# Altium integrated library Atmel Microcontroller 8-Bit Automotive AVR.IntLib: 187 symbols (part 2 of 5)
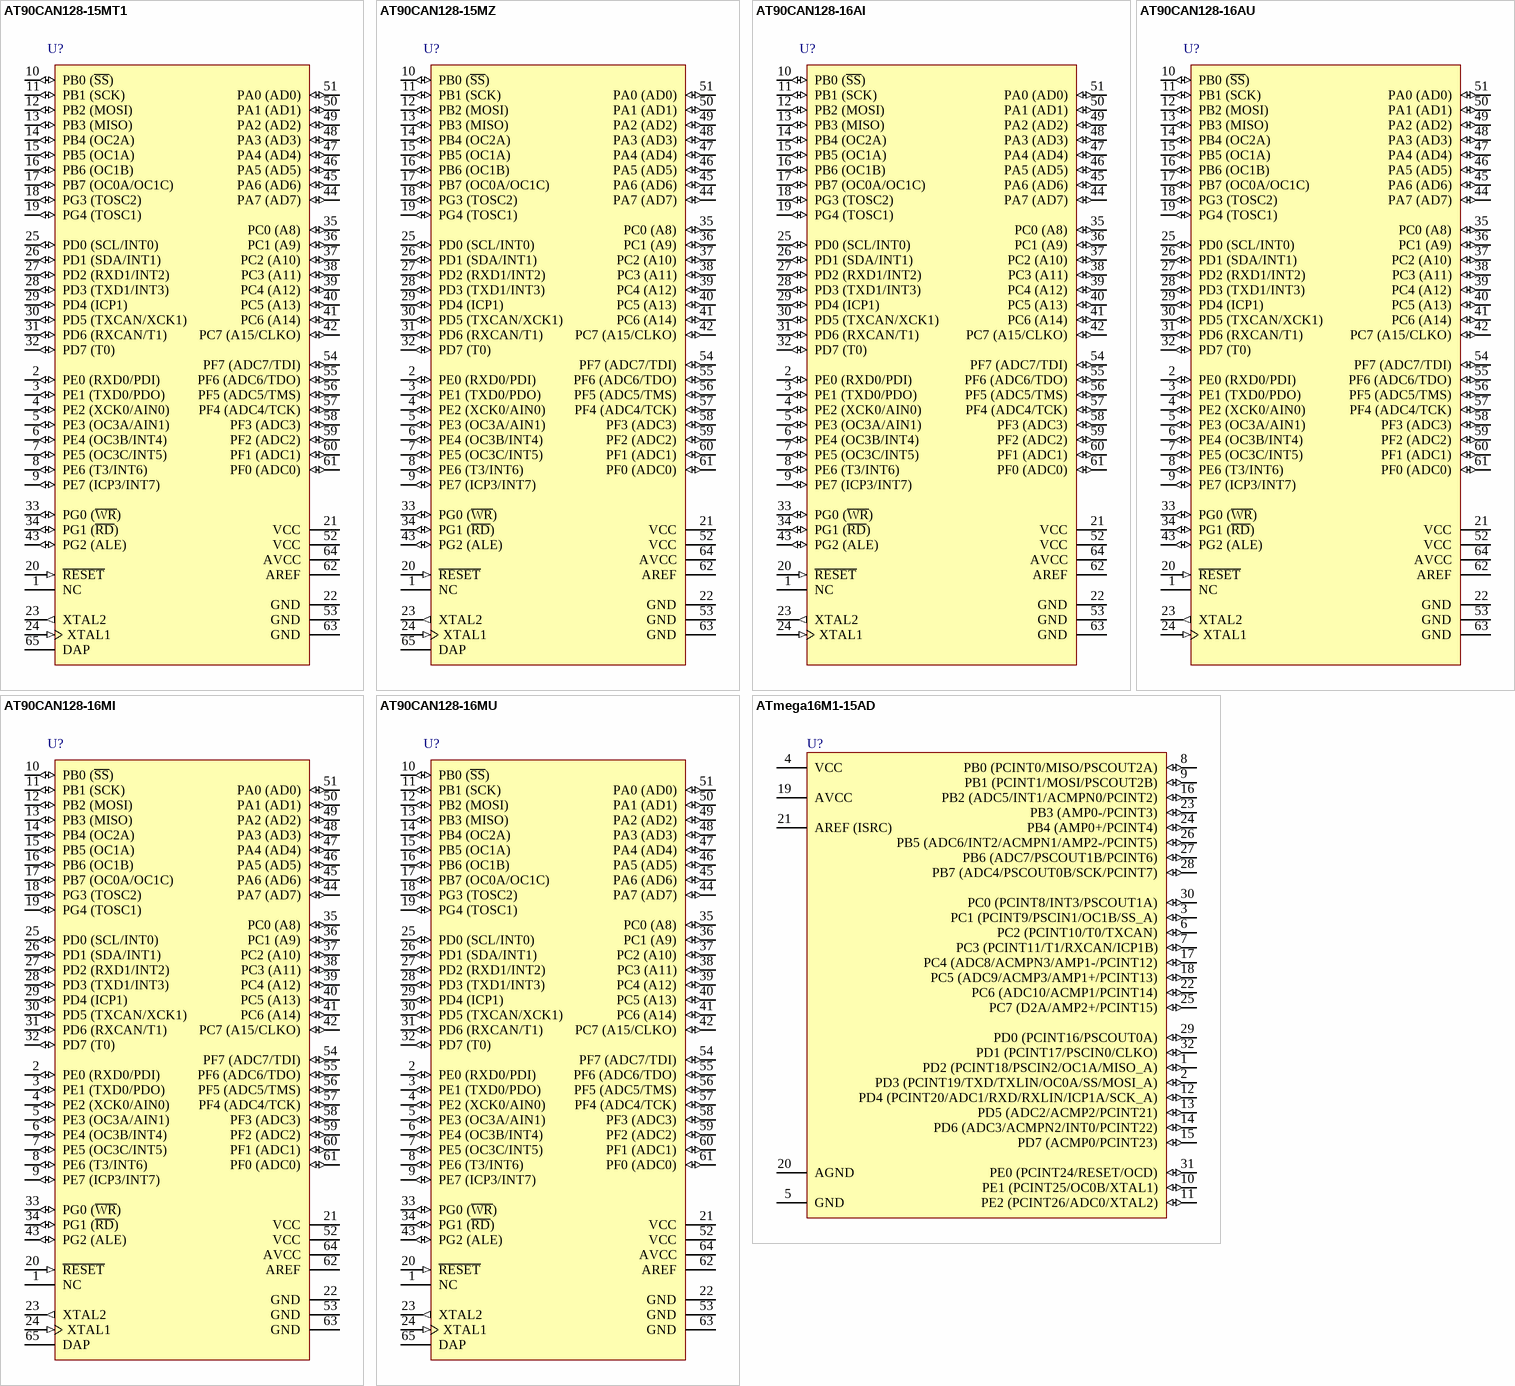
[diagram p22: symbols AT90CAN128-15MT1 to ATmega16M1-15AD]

## AT90CAN128-16MU
designator U?
8-bit AVR Microcontroller, 128KB Flash and CAN Controller, 53 GPIO pins, Industrial Grade (-40° to +85°C), 64-pin VQFN, Green
footprint Z64-2_N (QFN, 64-Leads, Body 9x9mm, Pitch 0.5mm, IPC Medium Density)
footprint Z64-2_L (QFN, 64-Leads, Body 9x9mm, Pitch 0.5mm, IPC High Density)
footprint Z64-2_M (QFN, 64-Leads, Body 9x9mm, Pitch 0.5mm, IPC Low Density)
pins: 1 NC, 2 PE0 (RXD0/PDI) (io), 3 PE1 (TXD0/PDO) (io), 4 PE2 (XCK0/AIN0) (io), 5 PE3 (OC3A/AIN1) (io), 6 PE4 (OC3B/INT4) (io), 7 PE5 (OC3C/INT5) (io), 8 PE6 (T3/INT6) (io), 9 PE7 (ICP3/INT7) (io), 10 PB0 (~{SS}) (io), 11 PB1 (SCK) (io), 12 PB2 (MOSI) (io), 13 PB3 (MISO) (io), 14 PB4 (OC2A) (io), 15 PB5 (OC1A) (io), 16 PB6 (OC1B) (io), 17 PB7 (OC0A/OC1C) (io), 18 PG3 (TOSC2) (io), 19 PG4 (TOSC1) (io), 20 ~{RESET} (in), 21 VCC (power), 22 GND (power), 23 XTAL2 (out), 24 XTAL1 (in), 25 PD0 (SCL/INT0) (io), 26 PD1 (SDA/INT1) (io), 27 PD2 (RXD1/INT2) (io), 28 PD3 (TXD1/INT3) (io), 29 PD4 (ICP1) (io), 30 PD5 (TXCAN/XCK1) (io), 31 PD6 (RXCAN/T1) (io), 32 PD7 (T0) (io), 33 PG0 (~{WR}) (io), 34 PG1 (~{RD}) (io), 35 PC0 (A8) (io), 36 PC1 (A9) (io), 37 PC2 (A10) (io), 38 PC3 (A11) (io), 39 PC4 (A12) (io), 40 PC5 (A13) (io), 41 PC6 (A14) (io), 42 PC7 (A15/CLKO) (io), 43 PG2 (ALE) (io), 44 PA7 (AD7) (io), 45 PA6 (AD6) (io), 46 PA5 (AD5) (io), 47 PA4 (AD4) (io), 48 PA3 (AD3) (io), 49 PA2 (AD2) (io), 50 PA1 (AD1) (io), 51 PA0 (AD0) (io), 52 VCC (power), 53 GND (power), 54 PF7 (ADC7/TDI) (io), 55 PF6 (ADC6/TDO) (io), 56 PF5 (ADC5/TMS) (io), 57 PF4 (ADC4/TCK) (io), 58 PF3 (ADC3) (io), 59 PF2 (ADC2) (io), 60 PF1 (ADC1) (io), 61 PF0 (ADC0) (io), 62 AREF (power), 63 GND (power), 64 AVCC (power), 65 DAP (power)

## ATmega16M1-15AD
designator U?
8-bit Automotive AVR Microcontroller, 16KB Flash, 512 Bytes EEPROM, 1KB SRAM, Extended Grade (-40°C to +150°C), 32-Pin TQFP
footprint 32MA_N (Thin QFP, 32-Leads, Body 7x7mm, Pitch 0.8mm, IPC Medium Density)
footprint 32MA_L (Thin QFP, 32-Leads, Body 7x7mm, Pitch 0.8mm, IPC High Density)
footprint 32MA_M (Thin QFP, 32-Leads, Body 7x7mm, Pitch 0.8mm, IPC Low Density)
pins: 1 PD2 (PCINT18/PSCIN2/OC1A/MISO_A) (io), 2 PD3 (PCINT19/TXD/TXLIN/OC0A/SS/MOSI_A) (io), 3 PC1 (PCINT9/PSCIN1/OC1B/SS_A) (io), 4 VCC (power), 5 GND (power), 6 PC2 (PCINT10/T0/TXCAN) (io), 7 PC3 (PCINT11/T1/RXCAN/ICP1B) (io), 8 PB0 (PCINT0/MISO/PSCOUT2A) (io), 9 PB1 (PCINT1/MOSI/PSCOUT2B) (io), 10 PE1 (PCINT25/OC0B/XTAL1) (io), 11 PE2 (PCINT26/ADC0/XTAL2) (io), 12 PD4 (PCINT20/ADC1/RXD/RXLIN/ICP1A/SCK_A) (io), 13 PD5 (ADC2/ACMP2/PCINT21) (io), 14 PD6 (ADC3/ACMPN2/INT0/PCINT22) (io), 15 PD7 (ACMP0/PCINT23) (io), 16 PB2 (ADC5/INT1/ACMPN0/PCINT2) (io), 17 PC4 (ADC8/ACMPN3/AMP1-/PCINT12) (io), 18 PC5 (ADC9/ACMP3/AMP1+/PCINT13) (io), 19 AVCC (power), 20 AGND (power), 21 AREF (ISRC) (power), 22 PC6 (ADC10/ACMP1/PCINT14) (io), 23 PB3 (AMP0-/PCINT3) (io), 24 PB4 (AMP0+/PCINT4) (io), 25 PC7 (D2A/AMP2+/PCINT15) (io), 26 PB5 (ADC6/INT2/ACMPN1/AMP2-/PCINT5) (io), 27 PB6 (ADC7/PSCOUT1B/PCINT6) (io), 28 PB7 (ADC4/PSCOUT0B/SCK/PCINT7) (io), 29 PD0 (PCINT16/PSCOUT0A) (io), 30 PC0 (PCINT8/INT3/PSCOUT1A) (io), 31 PE0 (PCINT24/RESET/OCD) (io), 32 PD1 (PCINT17/PSCIN0/CLKO) (io)

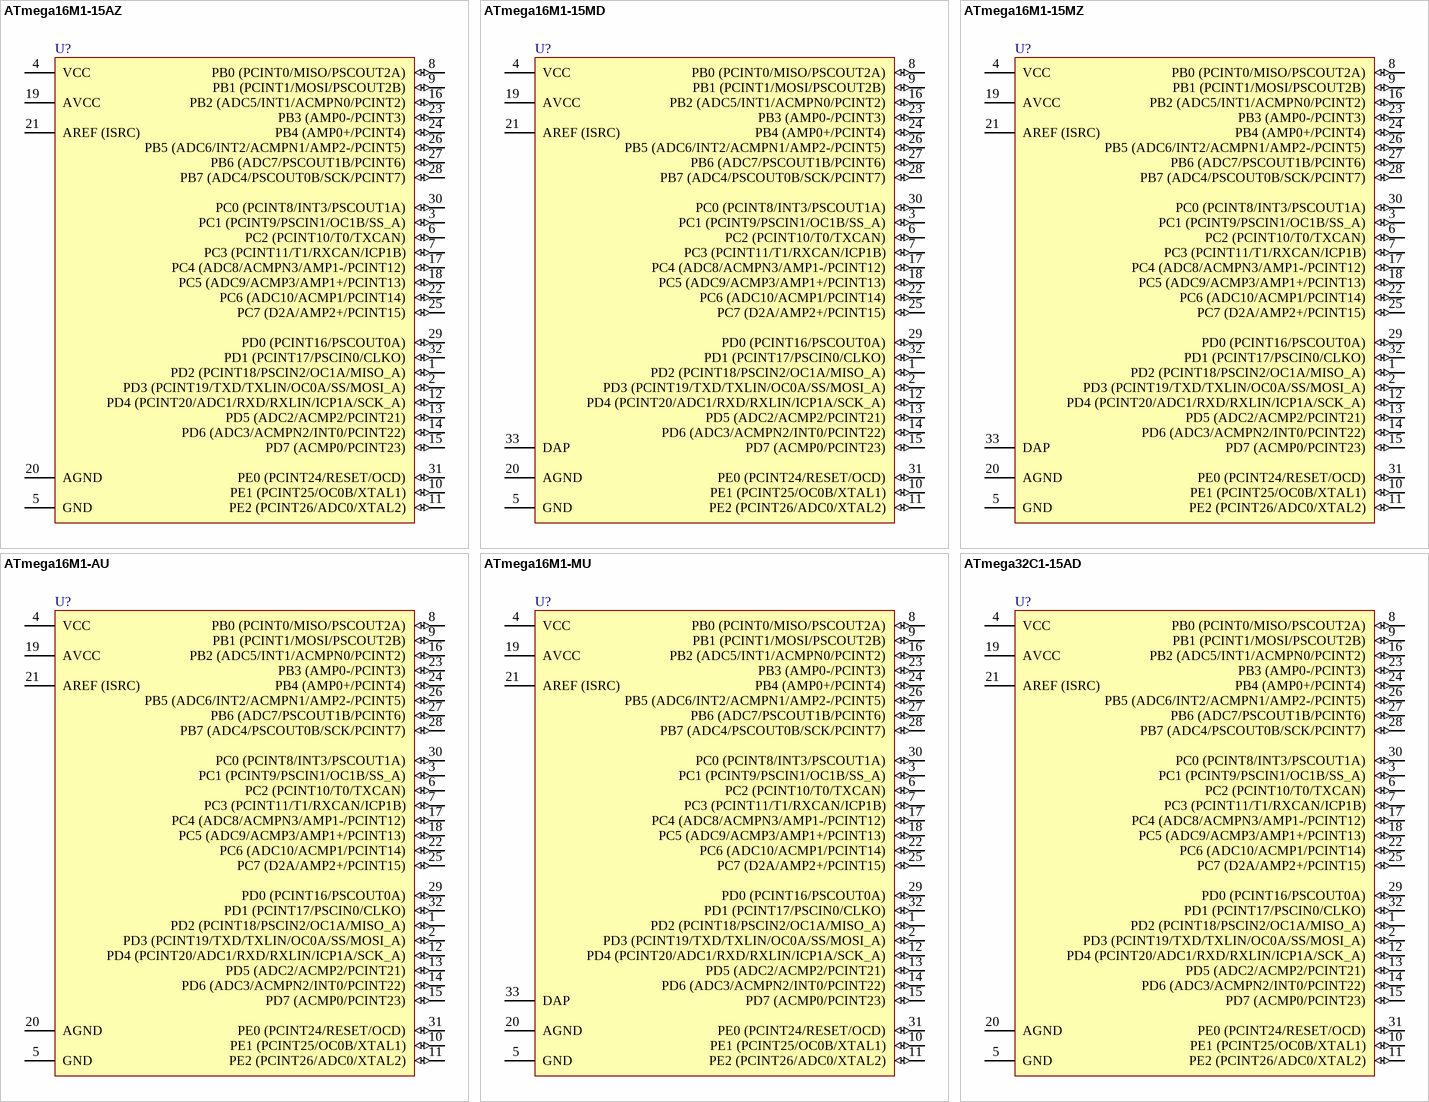
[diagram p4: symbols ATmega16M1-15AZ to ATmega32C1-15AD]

## ATmega16M1-15AZ
designator U?
8-bit Automotive AVR Microcontroller, 16KB Flash, 512 Bytes EEPROM, 1KB SRAM, PSC, Automotive Grade (-40°C to +125°C), 32-Pin TQFP
footprint 32MA_N (Thin QFP, 32-Leads, Body 7x7mm, Pitch 0.8mm, IPC Medium Density)
footprint 32MA_L (Thin QFP, 32-Leads, Body 7x7mm, Pitch 0.8mm, IPC High Density)
footprint 32MA_M (Thin QFP, 32-Leads, Body 7x7mm, Pitch 0.8mm, IPC Low Density)
pins: 1 PD2 (PCINT18/PSCIN2/OC1A/MISO_A) (io), 2 PD3 (PCINT19/TXD/TXLIN/OC0A/SS/MOSI_A) (io), 3 PC1 (PCINT9/PSCIN1/OC1B/SS_A) (io), 4 VCC (power), 5 GND (power), 6 PC2 (PCINT10/T0/TXCAN) (io), 7 PC3 (PCINT11/T1/RXCAN/ICP1B) (io), 8 PB0 (PCINT0/MISO/PSCOUT2A) (io), 9 PB1 (PCINT1/MOSI/PSCOUT2B) (io), 10 PE1 (PCINT25/OC0B/XTAL1) (io), 11 PE2 (PCINT26/ADC0/XTAL2) (io), 12 PD4 (PCINT20/ADC1/RXD/RXLIN/ICP1A/SCK_A) (io), 13 PD5 (ADC2/ACMP2/PCINT21) (io), 14 PD6 (ADC3/ACMPN2/INT0/PCINT22) (io), 15 PD7 (ACMP0/PCINT23) (io), 16 PB2 (ADC5/INT1/ACMPN0/PCINT2) (io), 17 PC4 (ADC8/ACMPN3/AMP1-/PCINT12) (io), 18 PC5 (ADC9/ACMP3/AMP1+/PCINT13) (io), 19 AVCC (power), 20 AGND (power), 21 AREF (ISRC) (power), 22 PC6 (ADC10/ACMP1/PCINT14) (io), 23 PB3 (AMP0-/PCINT3) (io), 24 PB4 (AMP0+/PCINT4) (io), 25 PC7 (D2A/AMP2+/PCINT15) (io), 26 PB5 (ADC6/INT2/ACMPN1/AMP2-/PCINT5) (io), 27 PB6 (ADC7/PSCOUT1B/PCINT6) (io), 28 PB7 (ADC4/PSCOUT0B/SCK/PCINT7) (io), 29 PD0 (PCINT16/PSCOUT0A) (io), 30 PC0 (PCINT8/INT3/PSCOUT1A) (io), 31 PE0 (PCINT24/RESET/OCD) (io), 32 PD1 (PCINT17/PSCIN0/CLKO) (io)

## ATmega16M1-15MD
designator U?
8-bit Automotive AVR Microcontroller, 16KB Flash, 512 Bytes EEPROM, 1KB SRAM, Extended Grade (-40°C to +150°C), 32-Pin VQFN
footprint 32PV_N (QFN, 32-Leads, Body 7x7 mm, Pitch 0.65mm, IPC Medium Density)
footprint 32PV_L (QFN, 32-Leads, Body 7x7 mm, Pitch 0.65mm, IPC High Density)
footprint 32PV_M (QFN, 32-Leads, Body 7x7 mm, Pitch 0.65mm, IPC Low Density)
pins: 1 PD2 (PCINT18/PSCIN2/OC1A/MISO_A) (io), 2 PD3 (PCINT19/TXD/TXLIN/OC0A/SS/MOSI_A) (io), 3 PC1 (PCINT9/PSCIN1/OC1B/SS_A) (io), 4 VCC (power), 5 GND (power), 6 PC2 (PCINT10/T0/TXCAN) (io), 7 PC3 (PCINT11/T1/RXCAN/ICP1B) (io), 8 PB0 (PCINT0/MISO/PSCOUT2A) (io), 9 PB1 (PCINT1/MOSI/PSCOUT2B) (io), 10 PE1 (PCINT25/OC0B/XTAL1) (io), 11 PE2 (PCINT26/ADC0/XTAL2) (io), 12 PD4 (PCINT20/ADC1/RXD/RXLIN/ICP1A/SCK_A) (io), 13 PD5 (ADC2/ACMP2/PCINT21) (io), 14 PD6 (ADC3/ACMPN2/INT0/PCINT22) (io), 15 PD7 (ACMP0/PCINT23) (io), 16 PB2 (ADC5/INT1/ACMPN0/PCINT2) (io), 17 PC4 (ADC8/ACMPN3/AMP1-/PCINT12) (io), 18 PC5 (ADC9/ACMP3/AMP1+/PCINT13) (io), 19 AVCC (power), 20 AGND (power), 21 AREF (ISRC) (power), 22 PC6 (ADC10/ACMP1/PCINT14) (io), 23 PB3 (AMP0-/PCINT3) (io), 24 PB4 (AMP0+/PCINT4) (io), 25 PC7 (D2A/AMP2+/PCINT15) (io), 26 PB5 (ADC6/INT2/ACMPN1/AMP2-/PCINT5) (io), 27 PB6 (ADC7/PSCOUT1B/PCINT6) (io), 28 PB7 (ADC4/PSCOUT0B/SCK/PCINT7) (io), 29 PD0 (PCINT16/PSCOUT0A) (io), 30 PC0 (PCINT8/INT3/PSCOUT1A) (io), 31 PE0 (PCINT24/RESET/OCD) (io), 32 PD1 (PCINT17/PSCIN0/CLKO) (io), 33 DAP (power)

## ATmega16M1-15MZ
designator U?
8-bit Automotive AVR Microcontroller, 16KB Flash, 512 Bytes EEPROM, 1KB SRAM, PSC, Automotive Grade (-40°C to +125°C), 32-Pin VQFN
footprint 32PV_N (QFN, 32-Leads, Body 7x7 mm, Pitch 0.65mm, IPC Medium Density)
footprint 32PV_L (QFN, 32-Leads, Body 7x7 mm, Pitch 0.65mm, IPC High Density)
footprint 32PV_M (QFN, 32-Leads, Body 7x7 mm, Pitch 0.65mm, IPC Low Density)
pins: 1 PD2 (PCINT18/PSCIN2/OC1A/MISO_A) (io), 2 PD3 (PCINT19/TXD/TXLIN/OC0A/SS/MOSI_A) (io), 3 PC1 (PCINT9/PSCIN1/OC1B/SS_A) (io), 4 VCC (power), 5 GND (power), 6 PC2 (PCINT10/T0/TXCAN) (io), 7 PC3 (PCINT11/T1/RXCAN/ICP1B) (io), 8 PB0 (PCINT0/MISO/PSCOUT2A) (io), 9 PB1 (PCINT1/MOSI/PSCOUT2B) (io), 10 PE1 (PCINT25/OC0B/XTAL1) (io), 11 PE2 (PCINT26/ADC0/XTAL2) (io), 12 PD4 (PCINT20/ADC1/RXD/RXLIN/ICP1A/SCK_A) (io), 13 PD5 (ADC2/ACMP2/PCINT21) (io), 14 PD6 (ADC3/ACMPN2/INT0/PCINT22) (io), 15 PD7 (ACMP0/PCINT23) (io), 16 PB2 (ADC5/INT1/ACMPN0/PCINT2) (io), 17 PC4 (ADC8/ACMPN3/AMP1-/PCINT12) (io), 18 PC5 (ADC9/ACMP3/AMP1+/PCINT13) (io), 19 AVCC (power), 20 AGND (power), 21 AREF (ISRC) (power), 22 PC6 (ADC10/ACMP1/PCINT14) (io), 23 PB3 (AMP0-/PCINT3) (io), 24 PB4 (AMP0+/PCINT4) (io), 25 PC7 (D2A/AMP2+/PCINT15) (io), 26 PB5 (ADC6/INT2/ACMPN1/AMP2-/PCINT5) (io), 27 PB6 (ADC7/PSCOUT1B/PCINT6) (io), 28 PB7 (ADC4/PSCOUT0B/SCK/PCINT7) (io), 29 PD0 (PCINT16/PSCOUT0A) (io), 30 PC0 (PCINT8/INT3/PSCOUT1A) (io), 31 PE0 (PCINT24/RESET/OCD) (io), 32 PD1 (PCINT17/PSCIN0/CLKO) (io), 33 DAP (power)

## ATmega16M1-AU
designator U?
8-bit AVR Microcontroller, 16KB Flash, 512 Bytes EEPROM, 1KB SRAM, Industrial Grade (-40° to +85°C), 32-Pin TQFP
footprint 32A_N (Thin QFP, 32-Leads, Body 7x7mm, Pitch 0.8mm, IPC Medium Density)
footprint 32A_L (Thin QFP, 32-Leads, Body 7x7mm, Pitch 0.8mm, IPC High Density)
footprint 32A_M (Thin QFP, 32-Leads, Body 7x7mm, Pitch 0.8mm, IPC Low Density)
pins: 1 PD2 (PCINT18/PSCIN2/OC1A/MISO_A) (io), 2 PD3 (PCINT19/TXD/TXLIN/OC0A/SS/MOSI_A) (io), 3 PC1 (PCINT9/PSCIN1/OC1B/SS_A) (io), 4 VCC (power), 5 GND (power), 6 PC2 (PCINT10/T0/TXCAN) (io), 7 PC3 (PCINT11/T1/RXCAN/ICP1B) (io), 8 PB0 (PCINT0/MISO/PSCOUT2A) (io), 9 PB1 (PCINT1/MOSI/PSCOUT2B) (io), 10 PE1 (PCINT25/OC0B/XTAL1) (io), 11 PE2 (PCINT26/ADC0/XTAL2) (io), 12 PD4 (PCINT20/ADC1/RXD/RXLIN/ICP1A/SCK_A) (io), 13 PD5 (ADC2/ACMP2/PCINT21) (io), 14 PD6 (ADC3/ACMPN2/INT0/PCINT22) (io), 15 PD7 (ACMP0/PCINT23) (io), 16 PB2 (ADC5/INT1/ACMPN0/PCINT2) (io), 17 PC4 (ADC8/ACMPN3/AMP1-/PCINT12) (io), 18 PC5 (ADC9/ACMP3/AMP1+/PCINT13) (io), 19 AVCC (power), 20 AGND (power), 21 AREF (ISRC) (power), 22 PC6 (ADC10/ACMP1/PCINT14) (io), 23 PB3 (AMP0-/PCINT3) (io), 24 PB4 (AMP0+/PCINT4) (io), 25 PC7 (D2A/AMP2+/PCINT15) (io), 26 PB5 (ADC6/INT2/ACMPN1/AMP2-/PCINT5) (io), 27 PB6 (ADC7/PSCOUT1B/PCINT6) (io), 28 PB7 (ADC4/PSCOUT0B/SCK/PCINT7) (io), 29 PD0 (PCINT16/PSCOUT0A) (io), 30 PC0 (PCINT8/INT3/PSCOUT1A) (io), 31 PE0 (PCINT24/RESET/OCD) (io), 32 PD1 (PCINT17/PSCIN0/CLKO) (io)

## ATmega16M1-MU
designator U?
8-bit AVR Microcontroller, 16KB Flash, 512 Bytes EEPROM, 1KB SRAM, Industrial Grade (-40° to +85°C), 32-Pin MLF
footprint 32M1-A_N (QFN, 32-Leads, Body 5x5mm, Pitch 0.5mm, IPC Medium Density)
footprint 32M1-A_L (QFN, 32-Leads, Body 5x5mm, Pitch 0.5mm, IPC High Density)
footprint 32M1-A_M (QFN, 32-Leads, Body 5x5mm, Pitch 0.5mm, IPC Low Density)
pins: 1 PD2 (PCINT18/PSCIN2/OC1A/MISO_A) (io), 2 PD3 (PCINT19/TXD/TXLIN/OC0A/SS/MOSI_A) (io), 3 PC1 (PCINT9/PSCIN1/OC1B/SS_A) (io), 4 VCC (power), 5 GND (power), 6 PC2 (PCINT10/T0/TXCAN) (io), 7 PC3 (PCINT11/T1/RXCAN/ICP1B) (io), 8 PB0 (PCINT0/MISO/PSCOUT2A) (io), 9 PB1 (PCINT1/MOSI/PSCOUT2B) (io), 10 PE1 (PCINT25/OC0B/XTAL1) (io), 11 PE2 (PCINT26/ADC0/XTAL2) (io), 12 PD4 (PCINT20/ADC1/RXD/RXLIN/ICP1A/SCK_A) (io), 13 PD5 (ADC2/ACMP2/PCINT21) (io), 14 PD6 (ADC3/ACMPN2/INT0/PCINT22) (io), 15 PD7 (ACMP0/PCINT23) (io), 16 PB2 (ADC5/INT1/ACMPN0/PCINT2) (io), 17 PC4 (ADC8/ACMPN3/AMP1-/PCINT12) (io), 18 PC5 (ADC9/ACMP3/AMP1+/PCINT13) (io), 19 AVCC (power), 20 AGND (power), 21 AREF (ISRC) (power), 22 PC6 (ADC10/ACMP1/PCINT14) (io), 23 PB3 (AMP0-/PCINT3) (io), 24 PB4 (AMP0+/PCINT4) (io), 25 PC7 (D2A/AMP2+/PCINT15) (io), 26 PB5 (ADC6/INT2/ACMPN1/AMP2-/PCINT5) (io), 27 PB6 (ADC7/PSCOUT1B/PCINT6) (io), 28 PB7 (ADC4/PSCOUT0B/SCK/PCINT7) (io), 29 PD0 (PCINT16/PSCOUT0A) (io), 30 PC0 (PCINT8/INT3/PSCOUT1A) (io), 31 PE0 (PCINT24/RESET/OCD) (io), 32 PD1 (PCINT17/PSCIN0/CLKO) (io), 33 DAP (power)

## ATmega32C1-15AD
designator U?
8-bit Automotive AVR Microcontroller, 32KB Flash, 1KB EEPROM, 2KB SRAM, Extended Grade (-40°C to +150°C), 32-Pin TQFP
footprint 32MA_N (Thin QFP, 32-Leads, Body 7x7mm, Pitch 0.8mm, IPC Medium Density)
footprint 32MA_L (Thin QFP, 32-Leads, Body 7x7mm, Pitch 0.8mm, IPC High Density)
footprint 32MA_M (Thin QFP, 32-Leads, Body 7x7mm, Pitch 0.8mm, IPC Low Density)
pins: 1 PD2 (PCINT18/PSCIN2/OC1A/MISO_A) (io), 2 PD3 (PCINT19/TXD/TXLIN/OC0A/SS/MOSI_A) (io), 3 PC1 (PCINT9/PSCIN1/OC1B/SS_A) (io), 4 VCC (power), 5 GND (power), 6 PC2 (PCINT10/T0/TXCAN) (io), 7 PC3 (PCINT11/T1/RXCAN/ICP1B) (io), 8 PB0 (PCINT0/MISO/PSCOUT2A) (io), 9 PB1 (PCINT1/MOSI/PSCOUT2B) (io), 10 PE1 (PCINT25/OC0B/XTAL1) (io), 11 PE2 (PCINT26/ADC0/XTAL2) (io), 12 PD4 (PCINT20/ADC1/RXD/RXLIN/ICP1A/SCK_A) (io), 13 PD5 (ADC2/ACMP2/PCINT21) (io), 14 PD6 (ADC3/ACMPN2/INT0/PCINT22) (io), 15 PD7 (ACMP0/PCINT23) (io), 16 PB2 (ADC5/INT1/ACMPN0/PCINT2) (io), 17 PC4 (ADC8/ACMPN3/AMP1-/PCINT12) (io), 18 PC5 (ADC9/ACMP3/AMP1+/PCINT13) (io), 19 AVCC (power), 20 AGND (power), 21 AREF (ISRC) (power), 22 PC6 (ADC10/ACMP1/PCINT14) (io), 23 PB3 (AMP0-/PCINT3) (io), 24 PB4 (AMP0+/PCINT4) (io), 25 PC7 (D2A/AMP2+/PCINT15) (io), 26 PB5 (ADC6/INT2/ACMPN1/AMP2-/PCINT5) (io), 27 PB6 (ADC7/PSCOUT1B/PCINT6) (io), 28 PB7 (ADC4/PSCOUT0B/SCK/PCINT7) (io), 29 PD0 (PCINT16/PSCOUT0A) (io), 30 PC0 (PCINT8/INT3/PSCOUT1A) (io), 31 PE0 (PCINT24/RESET/OCD) (io), 32 PD1 (PCINT17/PSCIN0/CLKO) (io)

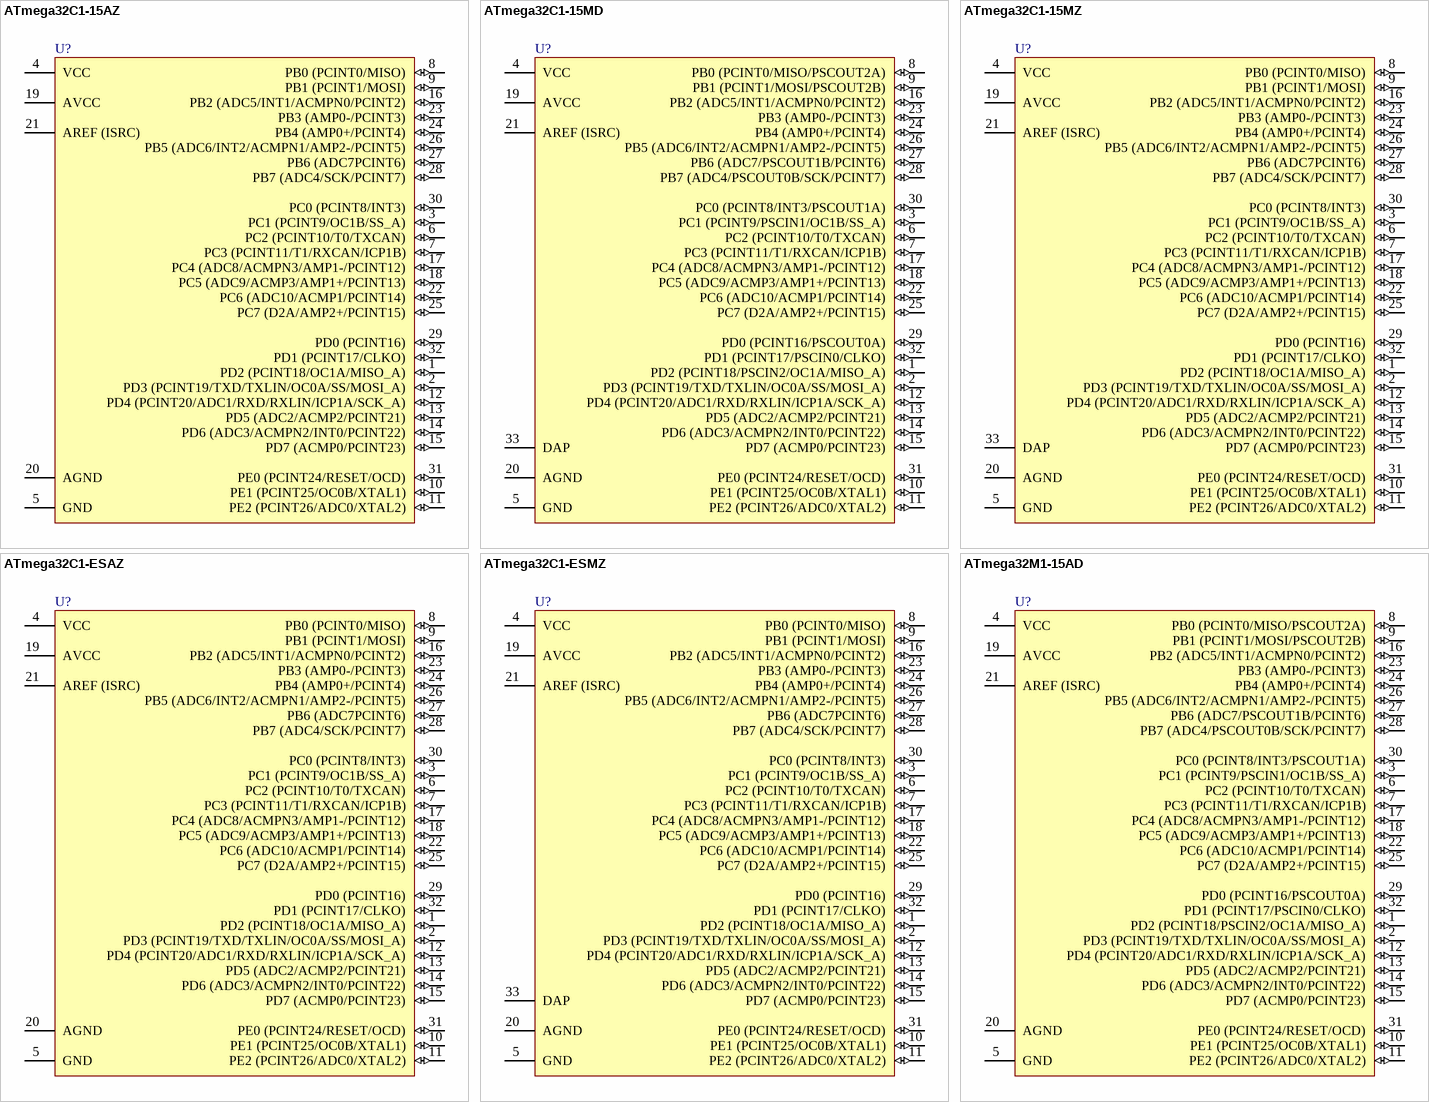
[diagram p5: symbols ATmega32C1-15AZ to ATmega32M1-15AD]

## ATmega32C1-15AZ
designator U?
8-bit Automotive AVR Microcontroller, 32KB Flash, 1KB EEPROM, 2KB SRAM, Automotive Grade (-40°C to +125°C), 32-Pin TQFP
footprint 32MA_N (Thin QFP, 32-Leads, Body 7x7mm, Pitch 0.8mm, IPC Medium Density)
footprint 32MA_L (Thin QFP, 32-Leads, Body 7x7mm, Pitch 0.8mm, IPC High Density)
footprint 32MA_M (Thin QFP, 32-Leads, Body 7x7mm, Pitch 0.8mm, IPC Low Density)
pins: 1 PD2 (PCINT18/OC1A/MISO_A) (io), 2 PD3 (PCINT19/TXD/TXLIN/OC0A/SS/MOSI_A) (io), 3 PC1 (PCINT9/OC1B/SS_A) (io), 4 VCC (power), 5 GND (power), 6 PC2 (PCINT10/T0/TXCAN) (io), 7 PC3 (PCINT11/T1/RXCAN/ICP1B) (io), 8 PB0 (PCINT0/MISO) (io), 9 PB1 (PCINT1/MOSI) (io), 10 PE1 (PCINT25/OC0B/XTAL1) (io), 11 PE2 (PCINT26/ADC0/XTAL2) (io), 12 PD4 (PCINT20/ADC1/RXD/RXLIN/ICP1A/SCK_A) (io), 13 PD5 (ADC2/ACMP2/PCINT21) (io), 14 PD6 (ADC3/ACMPN2/INT0/PCINT22) (io), 15 PD7 (ACMP0/PCINT23) (io), 16 PB2 (ADC5/INT1/ACMPN0/PCINT2) (io), 17 PC4 (ADC8/ACMPN3/AMP1-/PCINT12) (io), 18 PC5 (ADC9/ACMP3/AMP1+/PCINT13) (io), 19 AVCC (power), 20 AGND (power), 21 AREF (ISRC) (power), 22 PC6 (ADC10/ACMP1/PCINT14) (io), 23 PB3 (AMP0-/PCINT3) (io), 24 PB4 (AMP0+/PCINT4) (io), 25 PC7 (D2A/AMP2+/PCINT15) (io), 26 PB5 (ADC6/INT2/ACMPN1/AMP2-/PCINT5) (io), 27 PB6 (ADC7PCINT6) (io), 28 PB7 (ADC4/SCK/PCINT7) (io), 29 PD0 (PCINT16) (io), 30 PC0 (PCINT8/INT3) (io), 31 PE0 (PCINT24/RESET/OCD) (io), 32 PD1 (PCINT17/CLKO) (io)

## ATmega32C1-15MD
designator U?
8-bit Automotive AVR Microcontroller, 32KB Flash, 1KB EEPROM, 2KB SRAM, Extended Grade (-40°C to +150°C), 32-Pin VQFN
footprint 32PV_N (QFN, 32-Leads, Body 7x7 mm, Pitch 0.65mm, IPC Medium Density)
footprint 32PV_L (QFN, 32-Leads, Body 7x7 mm, Pitch 0.65mm, IPC High Density)
footprint 32PV_M (QFN, 32-Leads, Body 7x7 mm, Pitch 0.65mm, IPC Low Density)
pins: 1 PD2 (PCINT18/PSCIN2/OC1A/MISO_A) (io), 2 PD3 (PCINT19/TXD/TXLIN/OC0A/SS/MOSI_A) (io), 3 PC1 (PCINT9/PSCIN1/OC1B/SS_A) (io), 4 VCC (power), 5 GND (power), 6 PC2 (PCINT10/T0/TXCAN) (io), 7 PC3 (PCINT11/T1/RXCAN/ICP1B) (io), 8 PB0 (PCINT0/MISO/PSCOUT2A) (io), 9 PB1 (PCINT1/MOSI/PSCOUT2B) (io), 10 PE1 (PCINT25/OC0B/XTAL1) (io), 11 PE2 (PCINT26/ADC0/XTAL2) (io), 12 PD4 (PCINT20/ADC1/RXD/RXLIN/ICP1A/SCK_A) (io), 13 PD5 (ADC2/ACMP2/PCINT21) (io), 14 PD6 (ADC3/ACMPN2/INT0/PCINT22) (io), 15 PD7 (ACMP0/PCINT23) (io), 16 PB2 (ADC5/INT1/ACMPN0/PCINT2) (io), 17 PC4 (ADC8/ACMPN3/AMP1-/PCINT12) (io), 18 PC5 (ADC9/ACMP3/AMP1+/PCINT13) (io), 19 AVCC (power), 20 AGND (power), 21 AREF (ISRC) (power), 22 PC6 (ADC10/ACMP1/PCINT14) (io), 23 PB3 (AMP0-/PCINT3) (io), 24 PB4 (AMP0+/PCINT4) (io), 25 PC7 (D2A/AMP2+/PCINT15) (io), 26 PB5 (ADC6/INT2/ACMPN1/AMP2-/PCINT5) (io), 27 PB6 (ADC7/PSCOUT1B/PCINT6) (io), 28 PB7 (ADC4/PSCOUT0B/SCK/PCINT7) (io), 29 PD0 (PCINT16/PSCOUT0A) (io), 30 PC0 (PCINT8/INT3/PSCOUT1A) (io), 31 PE0 (PCINT24/RESET/OCD) (io), 32 PD1 (PCINT17/PSCIN0/CLKO) (io), 33 DAP (power)

## ATmega32C1-15MZ
designator U?
8-bit Automotive AVR Microcontroller, 32KB Flash, 1KB EEPROM, 2KB SRAM, Automotive Grade (-40°C to +125°C), 32-Pin VQFN
footprint 32PV_N (QFN, 32-Leads, Body 7x7 mm, Pitch 0.65mm, IPC Medium Density)
footprint 32PV_L (QFN, 32-Leads, Body 7x7 mm, Pitch 0.65mm, IPC High Density)
footprint 32PV_M (QFN, 32-Leads, Body 7x7 mm, Pitch 0.65mm, IPC Low Density)
pins: 1 PD2 (PCINT18/OC1A/MISO_A) (io), 2 PD3 (PCINT19/TXD/TXLIN/OC0A/SS/MOSI_A) (io), 3 PC1 (PCINT9/OC1B/SS_A) (io), 4 VCC (power), 5 GND (power), 6 PC2 (PCINT10/T0/TXCAN) (io), 7 PC3 (PCINT11/T1/RXCAN/ICP1B) (io), 8 PB0 (PCINT0/MISO) (io), 9 PB1 (PCINT1/MOSI) (io), 10 PE1 (PCINT25/OC0B/XTAL1) (io), 11 PE2 (PCINT26/ADC0/XTAL2) (io), 12 PD4 (PCINT20/ADC1/RXD/RXLIN/ICP1A/SCK_A) (io), 13 PD5 (ADC2/ACMP2/PCINT21) (io), 14 PD6 (ADC3/ACMPN2/INT0/PCINT22) (io), 15 PD7 (ACMP0/PCINT23) (io), 16 PB2 (ADC5/INT1/ACMPN0/PCINT2) (io), 17 PC4 (ADC8/ACMPN3/AMP1-/PCINT12) (io), 18 PC5 (ADC9/ACMP3/AMP1+/PCINT13) (io), 19 AVCC (power), 20 AGND (power), 21 AREF (ISRC) (power), 22 PC6 (ADC10/ACMP1/PCINT14) (io), 23 PB3 (AMP0-/PCINT3) (io), 24 PB4 (AMP0+/PCINT4) (io), 25 PC7 (D2A/AMP2+/PCINT15) (io), 26 PB5 (ADC6/INT2/ACMPN1/AMP2-/PCINT5) (io), 27 PB6 (ADC7PCINT6) (io), 28 PB7 (ADC4/SCK/PCINT7) (io), 29 PD0 (PCINT16) (io), 30 PC0 (PCINT8/INT3) (io), 31 PE0 (PCINT24/RESET/OCD) (io), 32 PD1 (PCINT17/CLKO) (io), 33 DAP (power)

## ATmega32C1-ESAZ
designator U?
8-bit Automotive AVR Microcontroller, 32KB Flash, 1KB EEPROM, 2KB SRAM, Engineering Sample, 32-Pin TQFP
footprint 32MA_N (Thin QFP, 32-Leads, Body 7x7mm, Pitch 0.8mm, IPC Medium Density)
footprint 32MA_L (Thin QFP, 32-Leads, Body 7x7mm, Pitch 0.8mm, IPC High Density)
footprint 32MA_M (Thin QFP, 32-Leads, Body 7x7mm, Pitch 0.8mm, IPC Low Density)
pins: 1 PD2 (PCINT18/OC1A/MISO_A) (io), 2 PD3 (PCINT19/TXD/TXLIN/OC0A/SS/MOSI_A) (io), 3 PC1 (PCINT9/OC1B/SS_A) (io), 4 VCC (power), 5 GND (power), 6 PC2 (PCINT10/T0/TXCAN) (io), 7 PC3 (PCINT11/T1/RXCAN/ICP1B) (io), 8 PB0 (PCINT0/MISO) (io), 9 PB1 (PCINT1/MOSI) (io), 10 PE1 (PCINT25/OC0B/XTAL1) (io), 11 PE2 (PCINT26/ADC0/XTAL2) (io), 12 PD4 (PCINT20/ADC1/RXD/RXLIN/ICP1A/SCK_A) (io), 13 PD5 (ADC2/ACMP2/PCINT21) (io), 14 PD6 (ADC3/ACMPN2/INT0/PCINT22) (io), 15 PD7 (ACMP0/PCINT23) (io), 16 PB2 (ADC5/INT1/ACMPN0/PCINT2) (io), 17 PC4 (ADC8/ACMPN3/AMP1-/PCINT12) (io), 18 PC5 (ADC9/ACMP3/AMP1+/PCINT13) (io), 19 AVCC (power), 20 AGND (power), 21 AREF (ISRC) (power), 22 PC6 (ADC10/ACMP1/PCINT14) (io), 23 PB3 (AMP0-/PCINT3) (io), 24 PB4 (AMP0+/PCINT4) (io), 25 PC7 (D2A/AMP2+/PCINT15) (io), 26 PB5 (ADC6/INT2/ACMPN1/AMP2-/PCINT5) (io), 27 PB6 (ADC7PCINT6) (io), 28 PB7 (ADC4/SCK/PCINT7) (io), 29 PD0 (PCINT16) (io), 30 PC0 (PCINT8/INT3) (io), 31 PE0 (PCINT24/RESET/OCD) (io), 32 PD1 (PCINT17/CLKO) (io)

## ATmega32C1-ESMZ
designator U?
8-bit Automotive AVR Microcontroller, 32KB Flash, 1KB EEPROM, 2KB SRAM, Engineering Sample, 32-Pin VQFN
footprint 32PV_N (QFN, 32-Leads, Body 7x7 mm, Pitch 0.65mm, IPC Medium Density)
footprint 32PV_L (QFN, 32-Leads, Body 7x7 mm, Pitch 0.65mm, IPC High Density)
footprint 32PV_M (QFN, 32-Leads, Body 7x7 mm, Pitch 0.65mm, IPC Low Density)
pins: 1 PD2 (PCINT18/OC1A/MISO_A) (io), 2 PD3 (PCINT19/TXD/TXLIN/OC0A/SS/MOSI_A) (io), 3 PC1 (PCINT9/OC1B/SS_A) (io), 4 VCC (power), 5 GND (power), 6 PC2 (PCINT10/T0/TXCAN) (io), 7 PC3 (PCINT11/T1/RXCAN/ICP1B) (io), 8 PB0 (PCINT0/MISO) (io), 9 PB1 (PCINT1/MOSI) (io), 10 PE1 (PCINT25/OC0B/XTAL1) (io), 11 PE2 (PCINT26/ADC0/XTAL2) (io), 12 PD4 (PCINT20/ADC1/RXD/RXLIN/ICP1A/SCK_A) (io), 13 PD5 (ADC2/ACMP2/PCINT21) (io), 14 PD6 (ADC3/ACMPN2/INT0/PCINT22) (io), 15 PD7 (ACMP0/PCINT23) (io), 16 PB2 (ADC5/INT1/ACMPN0/PCINT2) (io), 17 PC4 (ADC8/ACMPN3/AMP1-/PCINT12) (io), 18 PC5 (ADC9/ACMP3/AMP1+/PCINT13) (io), 19 AVCC (power), 20 AGND (power), 21 AREF (ISRC) (power), 22 PC6 (ADC10/ACMP1/PCINT14) (io), 23 PB3 (AMP0-/PCINT3) (io), 24 PB4 (AMP0+/PCINT4) (io), 25 PC7 (D2A/AMP2+/PCINT15) (io), 26 PB5 (ADC6/INT2/ACMPN1/AMP2-/PCINT5) (io), 27 PB6 (ADC7PCINT6) (io), 28 PB7 (ADC4/SCK/PCINT7) (io), 29 PD0 (PCINT16) (io), 30 PC0 (PCINT8/INT3) (io), 31 PE0 (PCINT24/RESET/OCD) (io), 32 PD1 (PCINT17/CLKO) (io), 33 DAP (power)

## ATmega32M1-15AD
designator U?
8-bit Automotive AVR Microcontroller, 32KB Flash, 1KB EEPROM, 2KB SRAM, Extended Grade (-40°C to +150°C), 32-Pin TQFP
footprint 32MA_N (Thin QFP, 32-Leads, Body 7x7mm, Pitch 0.8mm, IPC Medium Density)
footprint 32MA_L (Thin QFP, 32-Leads, Body 7x7mm, Pitch 0.8mm, IPC High Density)
footprint 32MA_M (Thin QFP, 32-Leads, Body 7x7mm, Pitch 0.8mm, IPC Low Density)
pins: 1 PD2 (PCINT18/PSCIN2/OC1A/MISO_A) (io), 2 PD3 (PCINT19/TXD/TXLIN/OC0A/SS/MOSI_A) (io), 3 PC1 (PCINT9/PSCIN1/OC1B/SS_A) (io), 4 VCC (power), 5 GND (power), 6 PC2 (PCINT10/T0/TXCAN) (io), 7 PC3 (PCINT11/T1/RXCAN/ICP1B) (io), 8 PB0 (PCINT0/MISO/PSCOUT2A) (io), 9 PB1 (PCINT1/MOSI/PSCOUT2B) (io), 10 PE1 (PCINT25/OC0B/XTAL1) (io), 11 PE2 (PCINT26/ADC0/XTAL2) (io), 12 PD4 (PCINT20/ADC1/RXD/RXLIN/ICP1A/SCK_A) (io), 13 PD5 (ADC2/ACMP2/PCINT21) (io), 14 PD6 (ADC3/ACMPN2/INT0/PCINT22) (io), 15 PD7 (ACMP0/PCINT23) (io), 16 PB2 (ADC5/INT1/ACMPN0/PCINT2) (io), 17 PC4 (ADC8/ACMPN3/AMP1-/PCINT12) (io), 18 PC5 (ADC9/ACMP3/AMP1+/PCINT13) (io), 19 AVCC (power), 20 AGND (power), 21 AREF (ISRC) (power), 22 PC6 (ADC10/ACMP1/PCINT14) (io), 23 PB3 (AMP0-/PCINT3) (io), 24 PB4 (AMP0+/PCINT4) (io), 25 PC7 (D2A/AMP2+/PCINT15) (io), 26 PB5 (ADC6/INT2/ACMPN1/AMP2-/PCINT5) (io), 27 PB6 (ADC7/PSCOUT1B/PCINT6) (io), 28 PB7 (ADC4/PSCOUT0B/SCK/PCINT7) (io), 29 PD0 (PCINT16/PSCOUT0A) (io), 30 PC0 (PCINT8/INT3/PSCOUT1A) (io), 31 PE0 (PCINT24/RESET/OCD) (io), 32 PD1 (PCINT17/PSCIN0/CLKO) (io)

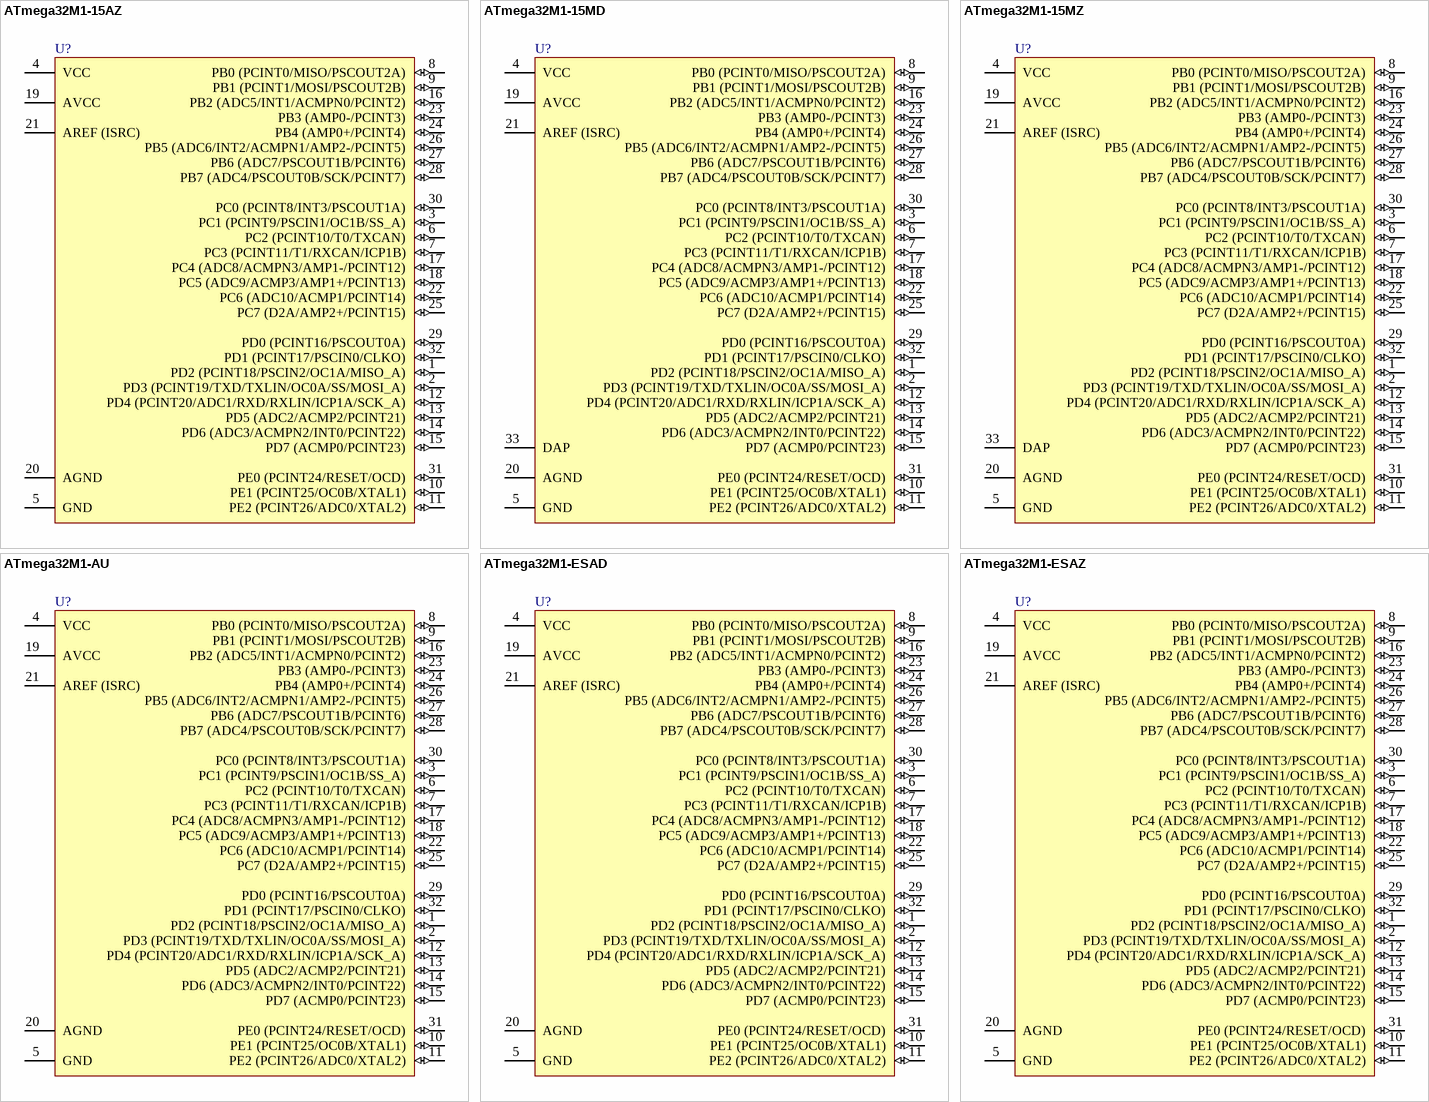
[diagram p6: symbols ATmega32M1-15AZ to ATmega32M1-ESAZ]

## ATmega32M1-15AZ
designator U?
8-bit Automotive AVR Microcontroller, 32KB Flash, 1KB EEPROM, 2KB SRAM, PSC, Automotive Grade (-40°C to +125°C), 32-Pin TQFP
footprint 32MA_N (Thin QFP, 32-Leads, Body 7x7mm, Pitch 0.8mm, IPC Medium Density)
footprint 32MA_L (Thin QFP, 32-Leads, Body 7x7mm, Pitch 0.8mm, IPC High Density)
footprint 32MA_M (Thin QFP, 32-Leads, Body 7x7mm, Pitch 0.8mm, IPC Low Density)
pins: 1 PD2 (PCINT18/PSCIN2/OC1A/MISO_A) (io), 2 PD3 (PCINT19/TXD/TXLIN/OC0A/SS/MOSI_A) (io), 3 PC1 (PCINT9/PSCIN1/OC1B/SS_A) (io), 4 VCC (power), 5 GND (power), 6 PC2 (PCINT10/T0/TXCAN) (io), 7 PC3 (PCINT11/T1/RXCAN/ICP1B) (io), 8 PB0 (PCINT0/MISO/PSCOUT2A) (io), 9 PB1 (PCINT1/MOSI/PSCOUT2B) (io), 10 PE1 (PCINT25/OC0B/XTAL1) (io), 11 PE2 (PCINT26/ADC0/XTAL2) (io), 12 PD4 (PCINT20/ADC1/RXD/RXLIN/ICP1A/SCK_A) (io), 13 PD5 (ADC2/ACMP2/PCINT21) (io), 14 PD6 (ADC3/ACMPN2/INT0/PCINT22) (io), 15 PD7 (ACMP0/PCINT23) (io), 16 PB2 (ADC5/INT1/ACMPN0/PCINT2) (io), 17 PC4 (ADC8/ACMPN3/AMP1-/PCINT12) (io), 18 PC5 (ADC9/ACMP3/AMP1+/PCINT13) (io), 19 AVCC (power), 20 AGND (power), 21 AREF (ISRC) (power), 22 PC6 (ADC10/ACMP1/PCINT14) (io), 23 PB3 (AMP0-/PCINT3) (io), 24 PB4 (AMP0+/PCINT4) (io), 25 PC7 (D2A/AMP2+/PCINT15) (io), 26 PB5 (ADC6/INT2/ACMPN1/AMP2-/PCINT5) (io), 27 PB6 (ADC7/PSCOUT1B/PCINT6) (io), 28 PB7 (ADC4/PSCOUT0B/SCK/PCINT7) (io), 29 PD0 (PCINT16/PSCOUT0A) (io), 30 PC0 (PCINT8/INT3/PSCOUT1A) (io), 31 PE0 (PCINT24/RESET/OCD) (io), 32 PD1 (PCINT17/PSCIN0/CLKO) (io)

## ATmega32M1-15MD
designator U?
8-bit Automotive AVR Microcontroller, 32KB Flash, 1KB EEPROM, 2KB SRAM, Extended Grade (-40°C to +150°C), 32-Pin VQFN
footprint 32PV_N (QFN, 32-Leads, Body 7x7 mm, Pitch 0.65mm, IPC Medium Density)
footprint 32PV_L (QFN, 32-Leads, Body 7x7 mm, Pitch 0.65mm, IPC High Density)
footprint 32PV_M (QFN, 32-Leads, Body 7x7 mm, Pitch 0.65mm, IPC Low Density)
pins: 1 PD2 (PCINT18/PSCIN2/OC1A/MISO_A) (io), 2 PD3 (PCINT19/TXD/TXLIN/OC0A/SS/MOSI_A) (io), 3 PC1 (PCINT9/PSCIN1/OC1B/SS_A) (io), 4 VCC (power), 5 GND (power), 6 PC2 (PCINT10/T0/TXCAN) (io), 7 PC3 (PCINT11/T1/RXCAN/ICP1B) (io), 8 PB0 (PCINT0/MISO/PSCOUT2A) (io), 9 PB1 (PCINT1/MOSI/PSCOUT2B) (io), 10 PE1 (PCINT25/OC0B/XTAL1) (io), 11 PE2 (PCINT26/ADC0/XTAL2) (io), 12 PD4 (PCINT20/ADC1/RXD/RXLIN/ICP1A/SCK_A) (io), 13 PD5 (ADC2/ACMP2/PCINT21) (io), 14 PD6 (ADC3/ACMPN2/INT0/PCINT22) (io), 15 PD7 (ACMP0/PCINT23) (io), 16 PB2 (ADC5/INT1/ACMPN0/PCINT2) (io), 17 PC4 (ADC8/ACMPN3/AMP1-/PCINT12) (io), 18 PC5 (ADC9/ACMP3/AMP1+/PCINT13) (io), 19 AVCC (power), 20 AGND (power), 21 AREF (ISRC) (power), 22 PC6 (ADC10/ACMP1/PCINT14) (io), 23 PB3 (AMP0-/PCINT3) (io), 24 PB4 (AMP0+/PCINT4) (io), 25 PC7 (D2A/AMP2+/PCINT15) (io), 26 PB5 (ADC6/INT2/ACMPN1/AMP2-/PCINT5) (io), 27 PB6 (ADC7/PSCOUT1B/PCINT6) (io), 28 PB7 (ADC4/PSCOUT0B/SCK/PCINT7) (io), 29 PD0 (PCINT16/PSCOUT0A) (io), 30 PC0 (PCINT8/INT3/PSCOUT1A) (io), 31 PE0 (PCINT24/RESET/OCD) (io), 32 PD1 (PCINT17/PSCIN0/CLKO) (io), 33 DAP (power)

## ATmega32M1-15MZ
designator U?
8-bit Automotive AVR Microcontroller, 32KB Flash, 1KB EEPROM, 2KB SRAM, PSC, Automotive Grade (-40°C to +125°C), 32-Pin VQFN
footprint 32PV_N (QFN, 32-Leads, Body 7x7 mm, Pitch 0.65mm, IPC Medium Density)
footprint 32PV_L (QFN, 32-Leads, Body 7x7 mm, Pitch 0.65mm, IPC High Density)
footprint 32PV_M (QFN, 32-Leads, Body 7x7 mm, Pitch 0.65mm, IPC Low Density)
pins: 1 PD2 (PCINT18/PSCIN2/OC1A/MISO_A) (io), 2 PD3 (PCINT19/TXD/TXLIN/OC0A/SS/MOSI_A) (io), 3 PC1 (PCINT9/PSCIN1/OC1B/SS_A) (io), 4 VCC (power), 5 GND (power), 6 PC2 (PCINT10/T0/TXCAN) (io), 7 PC3 (PCINT11/T1/RXCAN/ICP1B) (io), 8 PB0 (PCINT0/MISO/PSCOUT2A) (io), 9 PB1 (PCINT1/MOSI/PSCOUT2B) (io), 10 PE1 (PCINT25/OC0B/XTAL1) (io), 11 PE2 (PCINT26/ADC0/XTAL2) (io), 12 PD4 (PCINT20/ADC1/RXD/RXLIN/ICP1A/SCK_A) (io), 13 PD5 (ADC2/ACMP2/PCINT21) (io), 14 PD6 (ADC3/ACMPN2/INT0/PCINT22) (io), 15 PD7 (ACMP0/PCINT23) (io), 16 PB2 (ADC5/INT1/ACMPN0/PCINT2) (io), 17 PC4 (ADC8/ACMPN3/AMP1-/PCINT12) (io), 18 PC5 (ADC9/ACMP3/AMP1+/PCINT13) (io), 19 AVCC (power), 20 AGND (power), 21 AREF (ISRC) (power), 22 PC6 (ADC10/ACMP1/PCINT14) (io), 23 PB3 (AMP0-/PCINT3) (io), 24 PB4 (AMP0+/PCINT4) (io), 25 PC7 (D2A/AMP2+/PCINT15) (io), 26 PB5 (ADC6/INT2/ACMPN1/AMP2-/PCINT5) (io), 27 PB6 (ADC7/PSCOUT1B/PCINT6) (io), 28 PB7 (ADC4/PSCOUT0B/SCK/PCINT7) (io), 29 PD0 (PCINT16/PSCOUT0A) (io), 30 PC0 (PCINT8/INT3/PSCOUT1A) (io), 31 PE0 (PCINT24/RESET/OCD) (io), 32 PD1 (PCINT17/PSCIN0/CLKO) (io), 33 DAP (power)

## ATmega32M1-AU
designator U?
8-bit AVR Microcontroller, 32KB Flash, 1KB EEPROM, 2KB SRAM, Industrial Grade (-40° to +85°C), 32-Pin TQFP
footprint 32A_N (Thin QFP, 32-Leads, Body 7x7mm, Pitch 0.8mm, IPC Medium Density)
footprint 32A_L (Thin QFP, 32-Leads, Body 7x7mm, Pitch 0.8mm, IPC High Density)
footprint 32A_M (Thin QFP, 32-Leads, Body 7x7mm, Pitch 0.8mm, IPC Low Density)
pins: 1 PD2 (PCINT18/PSCIN2/OC1A/MISO_A) (io), 2 PD3 (PCINT19/TXD/TXLIN/OC0A/SS/MOSI_A) (io), 3 PC1 (PCINT9/PSCIN1/OC1B/SS_A) (io), 4 VCC (power), 5 GND (power), 6 PC2 (PCINT10/T0/TXCAN) (io), 7 PC3 (PCINT11/T1/RXCAN/ICP1B) (io), 8 PB0 (PCINT0/MISO/PSCOUT2A) (io), 9 PB1 (PCINT1/MOSI/PSCOUT2B) (io), 10 PE1 (PCINT25/OC0B/XTAL1) (io), 11 PE2 (PCINT26/ADC0/XTAL2) (io), 12 PD4 (PCINT20/ADC1/RXD/RXLIN/ICP1A/SCK_A) (io), 13 PD5 (ADC2/ACMP2/PCINT21) (io), 14 PD6 (ADC3/ACMPN2/INT0/PCINT22) (io), 15 PD7 (ACMP0/PCINT23) (io), 16 PB2 (ADC5/INT1/ACMPN0/PCINT2) (io), 17 PC4 (ADC8/ACMPN3/AMP1-/PCINT12) (io), 18 PC5 (ADC9/ACMP3/AMP1+/PCINT13) (io), 19 AVCC (power), 20 AGND (power), 21 AREF (ISRC) (power), 22 PC6 (ADC10/ACMP1/PCINT14) (io), 23 PB3 (AMP0-/PCINT3) (io), 24 PB4 (AMP0+/PCINT4) (io), 25 PC7 (D2A/AMP2+/PCINT15) (io), 26 PB5 (ADC6/INT2/ACMPN1/AMP2-/PCINT5) (io), 27 PB6 (ADC7/PSCOUT1B/PCINT6) (io), 28 PB7 (ADC4/PSCOUT0B/SCK/PCINT7) (io), 29 PD0 (PCINT16/PSCOUT0A) (io), 30 PC0 (PCINT8/INT3/PSCOUT1A) (io), 31 PE0 (PCINT24/RESET/OCD) (io), 32 PD1 (PCINT17/PSCIN0/CLKO) (io)

## ATmega32M1-ESAD
designator U?
8-bit Automotive AVR Microcontroller, 32KB Flash, 1KB EEPROM, 2KB SRAM, Engineering Sample, 32-Pin TQFP
footprint 32MA_N (Thin QFP, 32-Leads, Body 7x7mm, Pitch 0.8mm, IPC Medium Density)
footprint 32MA_L (Thin QFP, 32-Leads, Body 7x7mm, Pitch 0.8mm, IPC High Density)
footprint 32MA_M (Thin QFP, 32-Leads, Body 7x7mm, Pitch 0.8mm, IPC Low Density)
pins: 1 PD2 (PCINT18/PSCIN2/OC1A/MISO_A) (io), 2 PD3 (PCINT19/TXD/TXLIN/OC0A/SS/MOSI_A) (io), 3 PC1 (PCINT9/PSCIN1/OC1B/SS_A) (io), 4 VCC (power), 5 GND (power), 6 PC2 (PCINT10/T0/TXCAN) (io), 7 PC3 (PCINT11/T1/RXCAN/ICP1B) (io), 8 PB0 (PCINT0/MISO/PSCOUT2A) (io), 9 PB1 (PCINT1/MOSI/PSCOUT2B) (io), 10 PE1 (PCINT25/OC0B/XTAL1) (io), 11 PE2 (PCINT26/ADC0/XTAL2) (io), 12 PD4 (PCINT20/ADC1/RXD/RXLIN/ICP1A/SCK_A) (io), 13 PD5 (ADC2/ACMP2/PCINT21) (io), 14 PD6 (ADC3/ACMPN2/INT0/PCINT22) (io), 15 PD7 (ACMP0/PCINT23) (io), 16 PB2 (ADC5/INT1/ACMPN0/PCINT2) (io), 17 PC4 (ADC8/ACMPN3/AMP1-/PCINT12) (io), 18 PC5 (ADC9/ACMP3/AMP1+/PCINT13) (io), 19 AVCC (power), 20 AGND (power), 21 AREF (ISRC) (power), 22 PC6 (ADC10/ACMP1/PCINT14) (io), 23 PB3 (AMP0-/PCINT3) (io), 24 PB4 (AMP0+/PCINT4) (io), 25 PC7 (D2A/AMP2+/PCINT15) (io), 26 PB5 (ADC6/INT2/ACMPN1/AMP2-/PCINT5) (io), 27 PB6 (ADC7/PSCOUT1B/PCINT6) (io), 28 PB7 (ADC4/PSCOUT0B/SCK/PCINT7) (io), 29 PD0 (PCINT16/PSCOUT0A) (io), 30 PC0 (PCINT8/INT3/PSCOUT1A) (io), 31 PE0 (PCINT24/RESET/OCD) (io), 32 PD1 (PCINT17/PSCIN0/CLKO) (io)

## ATmega32M1-ESAZ
designator U?
8-bit Automotive AVR Microcontroller, 32KB Flash, 1KB EEPROM, 2KB SRAM, PSC, Engineering Sample, 32-Pin TQFP
footprint 32MA_N (Thin QFP, 32-Leads, Body 7x7mm, Pitch 0.8mm, IPC Medium Density)
footprint 32MA_L (Thin QFP, 32-Leads, Body 7x7mm, Pitch 0.8mm, IPC High Density)
footprint 32MA_M (Thin QFP, 32-Leads, Body 7x7mm, Pitch 0.8mm, IPC Low Density)
pins: 1 PD2 (PCINT18/PSCIN2/OC1A/MISO_A) (io), 2 PD3 (PCINT19/TXD/TXLIN/OC0A/SS/MOSI_A) (io), 3 PC1 (PCINT9/PSCIN1/OC1B/SS_A) (io), 4 VCC (power), 5 GND (power), 6 PC2 (PCINT10/T0/TXCAN) (io), 7 PC3 (PCINT11/T1/RXCAN/ICP1B) (io), 8 PB0 (PCINT0/MISO/PSCOUT2A) (io), 9 PB1 (PCINT1/MOSI/PSCOUT2B) (io), 10 PE1 (PCINT25/OC0B/XTAL1) (io), 11 PE2 (PCINT26/ADC0/XTAL2) (io), 12 PD4 (PCINT20/ADC1/RXD/RXLIN/ICP1A/SCK_A) (io), 13 PD5 (ADC2/ACMP2/PCINT21) (io), 14 PD6 (ADC3/ACMPN2/INT0/PCINT22) (io), 15 PD7 (ACMP0/PCINT23) (io), 16 PB2 (ADC5/INT1/ACMPN0/PCINT2) (io), 17 PC4 (ADC8/ACMPN3/AMP1-/PCINT12) (io), 18 PC5 (ADC9/ACMP3/AMP1+/PCINT13) (io), 19 AVCC (power), 20 AGND (power), 21 AREF (ISRC) (power), 22 PC6 (ADC10/ACMP1/PCINT14) (io), 23 PB3 (AMP0-/PCINT3) (io), 24 PB4 (AMP0+/PCINT4) (io), 25 PC7 (D2A/AMP2+/PCINT15) (io), 26 PB5 (ADC6/INT2/ACMPN1/AMP2-/PCINT5) (io), 27 PB6 (ADC7/PSCOUT1B/PCINT6) (io), 28 PB7 (ADC4/PSCOUT0B/SCK/PCINT7) (io), 29 PD0 (PCINT16/PSCOUT0A) (io), 30 PC0 (PCINT8/INT3/PSCOUT1A) (io), 31 PE0 (PCINT24/RESET/OCD) (io), 32 PD1 (PCINT17/PSCIN0/CLKO) (io)

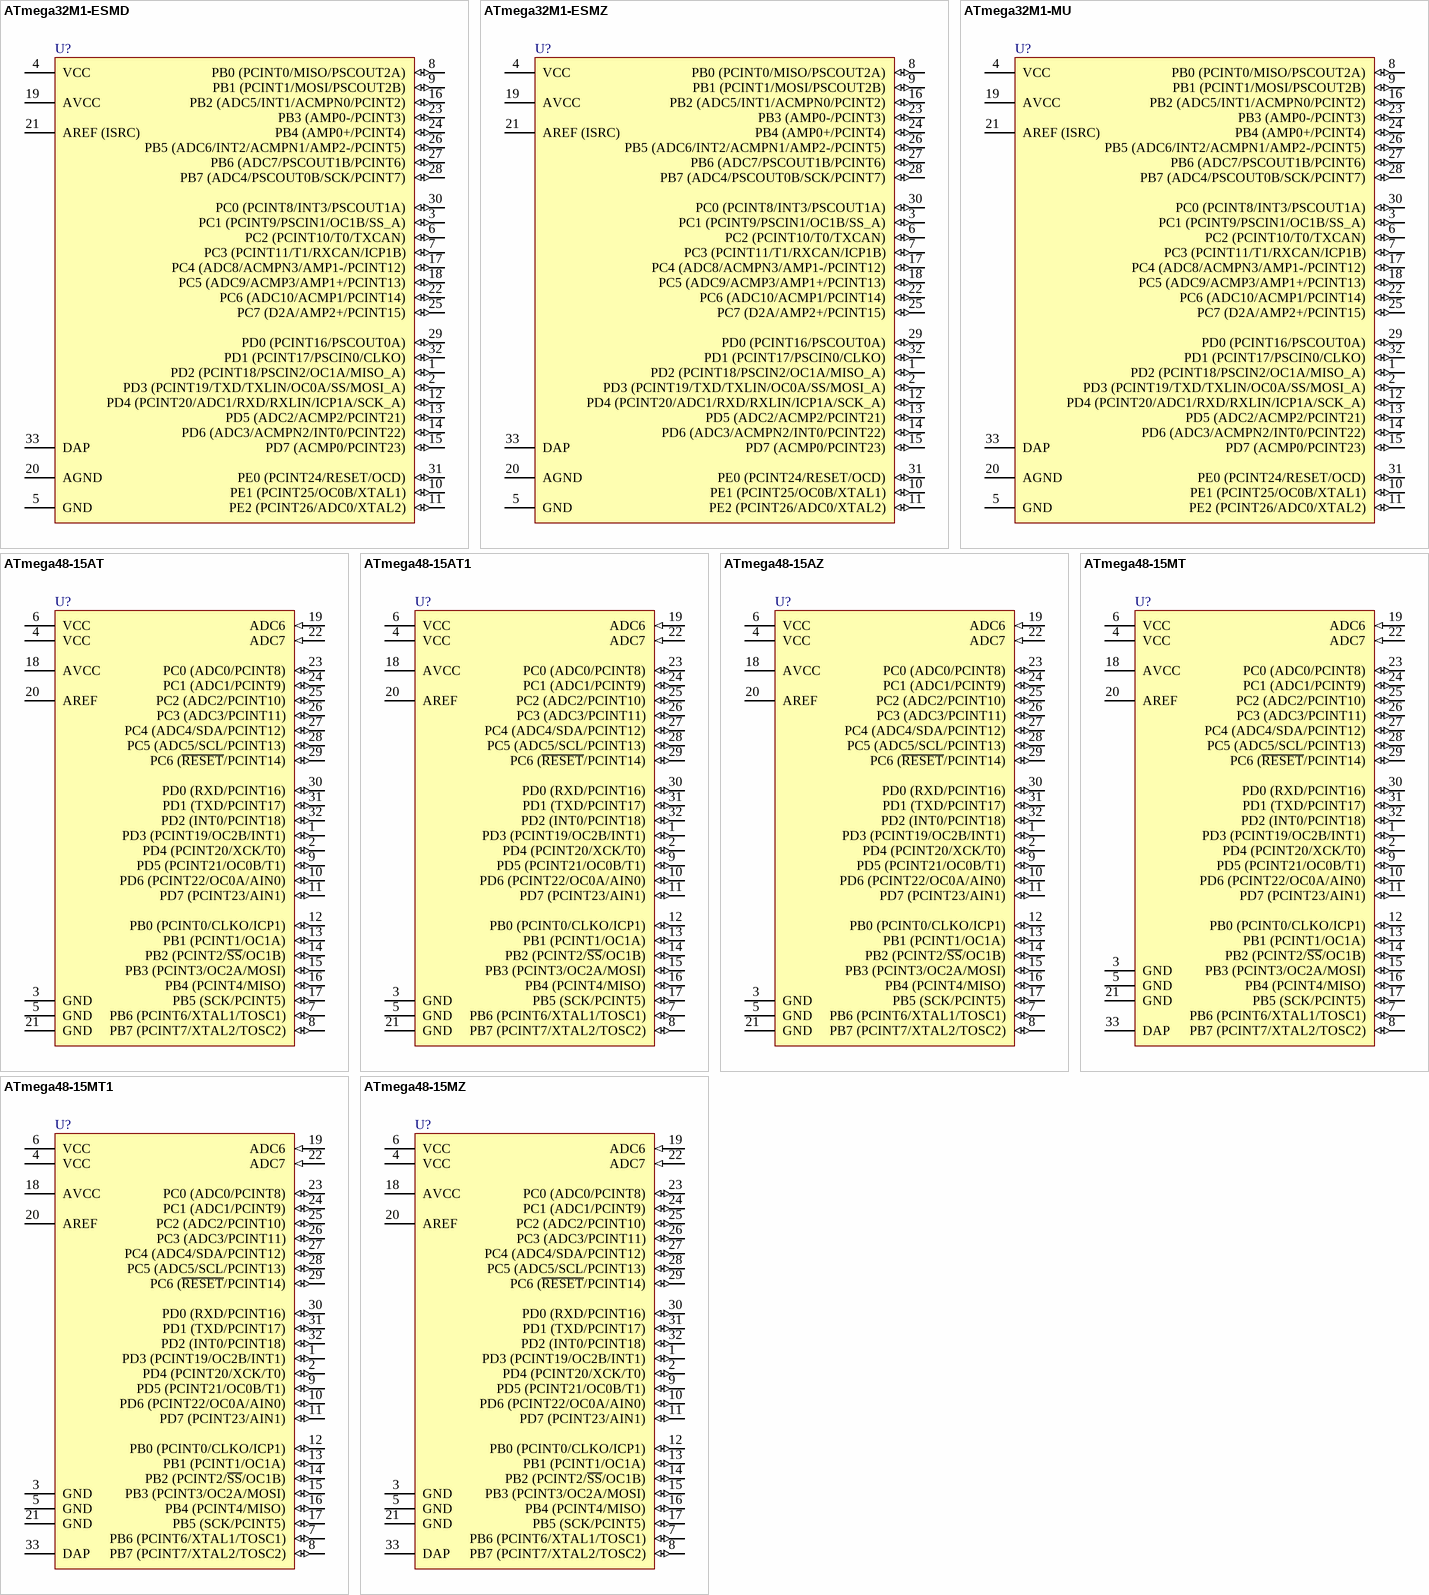
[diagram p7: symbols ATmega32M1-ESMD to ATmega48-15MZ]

## ATmega32M1-ESMD
designator U?
8-bit Automotive AVR Microcontroller, 32KB Flash, 1KB EEPROM, 2KB SRAM, Engineering Sample, 32-Pin VQFN
footprint 32PV_N (QFN, 32-Leads, Body 7x7 mm, Pitch 0.65mm, IPC Medium Density)
footprint 32PV_L (QFN, 32-Leads, Body 7x7 mm, Pitch 0.65mm, IPC High Density)
footprint 32PV_M (QFN, 32-Leads, Body 7x7 mm, Pitch 0.65mm, IPC Low Density)
pins: 1 PD2 (PCINT18/PSCIN2/OC1A/MISO_A) (io), 2 PD3 (PCINT19/TXD/TXLIN/OC0A/SS/MOSI_A) (io), 3 PC1 (PCINT9/PSCIN1/OC1B/SS_A) (io), 4 VCC (power), 5 GND (power), 6 PC2 (PCINT10/T0/TXCAN) (io), 7 PC3 (PCINT11/T1/RXCAN/ICP1B) (io), 8 PB0 (PCINT0/MISO/PSCOUT2A) (io), 9 PB1 (PCINT1/MOSI/PSCOUT2B) (io), 10 PE1 (PCINT25/OC0B/XTAL1) (io), 11 PE2 (PCINT26/ADC0/XTAL2) (io), 12 PD4 (PCINT20/ADC1/RXD/RXLIN/ICP1A/SCK_A) (io), 13 PD5 (ADC2/ACMP2/PCINT21) (io), 14 PD6 (ADC3/ACMPN2/INT0/PCINT22) (io), 15 PD7 (ACMP0/PCINT23) (io), 16 PB2 (ADC5/INT1/ACMPN0/PCINT2) (io), 17 PC4 (ADC8/ACMPN3/AMP1-/PCINT12) (io), 18 PC5 (ADC9/ACMP3/AMP1+/PCINT13) (io), 19 AVCC (power), 20 AGND (power), 21 AREF (ISRC) (power), 22 PC6 (ADC10/ACMP1/PCINT14) (io), 23 PB3 (AMP0-/PCINT3) (io), 24 PB4 (AMP0+/PCINT4) (io), 25 PC7 (D2A/AMP2+/PCINT15) (io), 26 PB5 (ADC6/INT2/ACMPN1/AMP2-/PCINT5) (io), 27 PB6 (ADC7/PSCOUT1B/PCINT6) (io), 28 PB7 (ADC4/PSCOUT0B/SCK/PCINT7) (io), 29 PD0 (PCINT16/PSCOUT0A) (io), 30 PC0 (PCINT8/INT3/PSCOUT1A) (io), 31 PE0 (PCINT24/RESET/OCD) (io), 32 PD1 (PCINT17/PSCIN0/CLKO) (io), 33 DAP (power)

## ATmega32M1-ESMZ
designator U?
8-bit Automotive AVR Microcontroller, 32KB Flash, 1KB EEPROM, 2KB SRAM, PSC, Engineering Sample, 32-Pin VQFN
footprint 32PV_N (QFN, 32-Leads, Body 7x7 mm, Pitch 0.65mm, IPC Medium Density)
footprint 32PV_L (QFN, 32-Leads, Body 7x7 mm, Pitch 0.65mm, IPC High Density)
footprint 32PV_M (QFN, 32-Leads, Body 7x7 mm, Pitch 0.65mm, IPC Low Density)
pins: 1 PD2 (PCINT18/PSCIN2/OC1A/MISO_A) (io), 2 PD3 (PCINT19/TXD/TXLIN/OC0A/SS/MOSI_A) (io), 3 PC1 (PCINT9/PSCIN1/OC1B/SS_A) (io), 4 VCC (power), 5 GND (power), 6 PC2 (PCINT10/T0/TXCAN) (io), 7 PC3 (PCINT11/T1/RXCAN/ICP1B) (io), 8 PB0 (PCINT0/MISO/PSCOUT2A) (io), 9 PB1 (PCINT1/MOSI/PSCOUT2B) (io), 10 PE1 (PCINT25/OC0B/XTAL1) (io), 11 PE2 (PCINT26/ADC0/XTAL2) (io), 12 PD4 (PCINT20/ADC1/RXD/RXLIN/ICP1A/SCK_A) (io), 13 PD5 (ADC2/ACMP2/PCINT21) (io), 14 PD6 (ADC3/ACMPN2/INT0/PCINT22) (io), 15 PD7 (ACMP0/PCINT23) (io), 16 PB2 (ADC5/INT1/ACMPN0/PCINT2) (io), 17 PC4 (ADC8/ACMPN3/AMP1-/PCINT12) (io), 18 PC5 (ADC9/ACMP3/AMP1+/PCINT13) (io), 19 AVCC (power), 20 AGND (power), 21 AREF (ISRC) (power), 22 PC6 (ADC10/ACMP1/PCINT14) (io), 23 PB3 (AMP0-/PCINT3) (io), 24 PB4 (AMP0+/PCINT4) (io), 25 PC7 (D2A/AMP2+/PCINT15) (io), 26 PB5 (ADC6/INT2/ACMPN1/AMP2-/PCINT5) (io), 27 PB6 (ADC7/PSCOUT1B/PCINT6) (io), 28 PB7 (ADC4/PSCOUT0B/SCK/PCINT7) (io), 29 PD0 (PCINT16/PSCOUT0A) (io), 30 PC0 (PCINT8/INT3/PSCOUT1A) (io), 31 PE0 (PCINT24/RESET/OCD) (io), 32 PD1 (PCINT17/PSCIN0/CLKO) (io), 33 DAP (power)

## ATmega32M1-MU
designator U?
8-bit AVR Microcontroller, 32KB Flash, 1KB EEPROM, 2KB SRAM, Industrial Grade (-40° to +85°C), 32-Pin MLF
footprint 32M1-A_N (QFN, 32-Leads, Body 5x5mm, Pitch 0.5mm, IPC Medium Density)
footprint 32M1-A_L (QFN, 32-Leads, Body 5x5mm, Pitch 0.5mm, IPC High Density)
footprint 32M1-A_M (QFN, 32-Leads, Body 5x5mm, Pitch 0.5mm, IPC Low Density)
pins: 1 PD2 (PCINT18/PSCIN2/OC1A/MISO_A) (io), 2 PD3 (PCINT19/TXD/TXLIN/OC0A/SS/MOSI_A) (io), 3 PC1 (PCINT9/PSCIN1/OC1B/SS_A) (io), 4 VCC (power), 5 GND (power), 6 PC2 (PCINT10/T0/TXCAN) (io), 7 PC3 (PCINT11/T1/RXCAN/ICP1B) (io), 8 PB0 (PCINT0/MISO/PSCOUT2A) (io), 9 PB1 (PCINT1/MOSI/PSCOUT2B) (io), 10 PE1 (PCINT25/OC0B/XTAL1) (io), 11 PE2 (PCINT26/ADC0/XTAL2) (io), 12 PD4 (PCINT20/ADC1/RXD/RXLIN/ICP1A/SCK_A) (io), 13 PD5 (ADC2/ACMP2/PCINT21) (io), 14 PD6 (ADC3/ACMPN2/INT0/PCINT22) (io), 15 PD7 (ACMP0/PCINT23) (io), 16 PB2 (ADC5/INT1/ACMPN0/PCINT2) (io), 17 PC4 (ADC8/ACMPN3/AMP1-/PCINT12) (io), 18 PC5 (ADC9/ACMP3/AMP1+/PCINT13) (io), 19 AVCC (power), 20 AGND (power), 21 AREF (ISRC) (power), 22 PC6 (ADC10/ACMP1/PCINT14) (io), 23 PB3 (AMP0-/PCINT3) (io), 24 PB4 (AMP0+/PCINT4) (io), 25 PC7 (D2A/AMP2+/PCINT15) (io), 26 PB5 (ADC6/INT2/ACMPN1/AMP2-/PCINT5) (io), 27 PB6 (ADC7/PSCOUT1B/PCINT6) (io), 28 PB7 (ADC4/PSCOUT0B/SCK/PCINT7) (io), 29 PD0 (PCINT16/PSCOUT0A) (io), 30 PC0 (PCINT8/INT3/PSCOUT1A) (io), 31 PE0 (PCINT24/RESET/OCD) (io), 32 PD1 (PCINT17/PSCIN0/CLKO) (io), 33 DAP (power)

## ATmega48-15AT
designator U?
8-bit Automotive AVR Microcontroller, 4KB Flash, 256 Bytes EEPROM, 512 Bytes SRAM, Automotive Grade (-40°C to +85°C), 32-Pin TQFP
footprint 32MA_N (Thin QFP, 32-Leads, Body 7x7mm, Pitch 0.8mm, IPC Medium Density)
footprint 32MA_L (Thin QFP, 32-Leads, Body 7x7mm, Pitch 0.8mm, IPC High Density)
footprint 32MA_M (Thin QFP, 32-Leads, Body 7x7mm, Pitch 0.8mm, IPC Low Density)
pins: 1 PD3 (PCINT19/OC2B/INT1) (io), 2 PD4 (PCINT20/XCK/T0) (io), 3 GND (power), 4 VCC (power), 5 GND (power), 6 VCC (power), 7 PB6 (PCINT6/XTAL1/TOSC1) (io), 8 PB7 (PCINT7/XTAL2/TOSC2) (io), 9 PD5 (PCINT21/OC0B/T1) (io), 10 PD6 (PCINT22/OC0A/AIN0) (io), 11 PD7 (PCINT23/AIN1) (io), 12 PB0 (PCINT0/CLKO/ICP1) (io), 13 PB1 (PCINT1/OC1A) (io), 14 PB2 (PCINT2/~{SS}/OC1B) (io), 15 PB3 (PCINT3/OC2A/MOSI) (io), 16 PB4 (PCINT4/MISO) (io), 17 PB5 (SCK/PCINT5) (io), 18 AVCC (power), 19 ADC6 (in), 20 AREF, 21 GND (power), 22 ADC7 (in), 23 PC0 (ADC0/PCINT8) (io), 24 PC1 (ADC1/PCINT9) (io), 25 PC2 (ADC2/PCINT10) (io), 26 PC3 (ADC3/PCINT11) (io), 27 PC4 (ADC4/SDA/PCINT12) (io), 28 PC5 (ADC5/SCL/PCINT13) (io), 29 PC6 (~{RESET}/PCINT14) (io), 30 PD0 (RXD/PCINT16) (io), 31 PD1 (TXD/PCINT17) (io), 32 PD2 (INT0/PCINT18) (io)

## ATmega48-15AT1
designator U?
8-bit Automotive AVR Microcontroller, 4KB Flash, 256 Bytes EEPROM, 512 Bytes SRAM, Automotive Grade (-40°C to +105°C), 32-Pin TQFP
footprint 32MA_N (Thin QFP, 32-Leads, Body 7x7mm, Pitch 0.8mm, IPC Medium Density)
footprint 32MA_L (Thin QFP, 32-Leads, Body 7x7mm, Pitch 0.8mm, IPC High Density)
footprint 32MA_M (Thin QFP, 32-Leads, Body 7x7mm, Pitch 0.8mm, IPC Low Density)
pins: 1 PD3 (PCINT19/OC2B/INT1) (io), 2 PD4 (PCINT20/XCK/T0) (io), 3 GND (power), 4 VCC (power), 5 GND (power), 6 VCC (power), 7 PB6 (PCINT6/XTAL1/TOSC1) (io), 8 PB7 (PCINT7/XTAL2/TOSC2) (io), 9 PD5 (PCINT21/OC0B/T1) (io), 10 PD6 (PCINT22/OC0A/AIN0) (io), 11 PD7 (PCINT23/AIN1) (io), 12 PB0 (PCINT0/CLKO/ICP1) (io), 13 PB1 (PCINT1/OC1A) (io), 14 PB2 (PCINT2/~{SS}/OC1B) (io), 15 PB3 (PCINT3/OC2A/MOSI) (io), 16 PB4 (PCINT4/MISO) (io), 17 PB5 (SCK/PCINT5) (io), 18 AVCC (power), 19 ADC6 (in), 20 AREF, 21 GND (power), 22 ADC7 (in), 23 PC0 (ADC0/PCINT8) (io), 24 PC1 (ADC1/PCINT9) (io), 25 PC2 (ADC2/PCINT10) (io), 26 PC3 (ADC3/PCINT11) (io), 27 PC4 (ADC4/SDA/PCINT12) (io), 28 PC5 (ADC5/SCL/PCINT13) (io), 29 PC6 (~{RESET}/PCINT14) (io), 30 PD0 (RXD/PCINT16) (io), 31 PD1 (TXD/PCINT17) (io), 32 PD2 (INT0/PCINT18) (io)

## ATmega48-15AZ
designator U?
8-bit Automotive AVR Microcontroller, 4KB Flash, 256 Bytes EEPROM, 512 Bytes SRAM, Automotive Grade (-40°C to +125°C), 32-Pin TQFP
footprint 32MA_N (Thin QFP, 32-Leads, Body 7x7mm, Pitch 0.8mm, IPC Medium Density)
footprint 32MA_L (Thin QFP, 32-Leads, Body 7x7mm, Pitch 0.8mm, IPC High Density)
footprint 32MA_M (Thin QFP, 32-Leads, Body 7x7mm, Pitch 0.8mm, IPC Low Density)
pins: 1 PD3 (PCINT19/OC2B/INT1) (io), 2 PD4 (PCINT20/XCK/T0) (io), 3 GND (power), 4 VCC (power), 5 GND (power), 6 VCC (power), 7 PB6 (PCINT6/XTAL1/TOSC1) (io), 8 PB7 (PCINT7/XTAL2/TOSC2) (io), 9 PD5 (PCINT21/OC0B/T1) (io), 10 PD6 (PCINT22/OC0A/AIN0) (io), 11 PD7 (PCINT23/AIN1) (io), 12 PB0 (PCINT0/CLKO/ICP1) (io), 13 PB1 (PCINT1/OC1A) (io), 14 PB2 (PCINT2/~{SS}/OC1B) (io), 15 PB3 (PCINT3/OC2A/MOSI) (io), 16 PB4 (PCINT4/MISO) (io), 17 PB5 (SCK/PCINT5) (io), 18 AVCC (power), 19 ADC6 (in), 20 AREF, 21 GND (power), 22 ADC7 (in), 23 PC0 (ADC0/PCINT8) (io), 24 PC1 (ADC1/PCINT9) (io), 25 PC2 (ADC2/PCINT10) (io), 26 PC3 (ADC3/PCINT11) (io), 27 PC4 (ADC4/SDA/PCINT12) (io), 28 PC5 (ADC5/SCL/PCINT13) (io), 29 PC6 (~{RESET}/PCINT14) (io), 30 PD0 (RXD/PCINT16) (io), 31 PD1 (TXD/PCINT17) (io), 32 PD2 (INT0/PCINT18) (io)

## ATmega48-15MT
designator U?
8-bit Automotive AVR Microcontroller, 4KB Flash, 256 Bytes EEPROM, 512 Bytes SRAM, Automotive Grade (-40°C to +85°C), 32-Pin VQFN
footprint 32PN_N (QFN, 32-Leads, Body 5x5mm, Pitch 0.5mm, IPC Medium Density)
footprint 32PN_L (QFN, 32-Leads, Body 5x5mm, Pitch 0.5mm, IPC High Density)
footprint 32PN_M (QFN, 32-Leads, Body 5x5mm, Pitch 0.5mm, IPC Low Density)
pins: 1 PD3 (PCINT19/OC2B/INT1) (io), 2 PD4 (PCINT20/XCK/T0) (io), 3 GND (power), 4 VCC (power), 5 GND (power), 6 VCC (power), 7 PB6 (PCINT6/XTAL1/TOSC1) (io), 8 PB7 (PCINT7/XTAL2/TOSC2) (io), 9 PD5 (PCINT21/OC0B/T1) (io), 10 PD6 (PCINT22/OC0A/AIN0) (io), 11 PD7 (PCINT23/AIN1) (io), 12 PB0 (PCINT0/CLKO/ICP1) (io), 13 PB1 (PCINT1/OC1A) (io), 14 PB2 (PCINT2/~{SS}/OC1B) (io), 15 PB3 (PCINT3/OC2A/MOSI) (io), 16 PB4 (PCINT4/MISO) (io), 17 PB5 (SCK/PCINT5) (io), 18 AVCC (power), 19 ADC6 (in), 20 AREF, 21 GND (power), 22 ADC7 (in), 23 PC0 (ADC0/PCINT8) (io), 24 PC1 (ADC1/PCINT9) (io), 25 PC2 (ADC2/PCINT10) (io), 26 PC3 (ADC3/PCINT11) (io), 27 PC4 (ADC4/SDA/PCINT12) (io), 28 PC5 (ADC5/SCL/PCINT13) (io), 29 PC6 (~{RESET}/PCINT14) (io), 30 PD0 (RXD/PCINT16) (io), 31 PD1 (TXD/PCINT17) (io), 32 PD2 (INT0/PCINT18) (io), 33 DAP (power)

## ATmega48-15MT1
designator U?
8-bit Automotive AVR Microcontroller, 4KB Flash, 256 Bytes EEPROM, 512 Bytes SRAM, Automotive Grade (-40°C to +105°C), 32-Pin VQFN
footprint 32PN_N (QFN, 32-Leads, Body 5x5mm, Pitch 0.5mm, IPC Medium Density)
footprint 32PN_L (QFN, 32-Leads, Body 5x5mm, Pitch 0.5mm, IPC High Density)
footprint 32PN_M (QFN, 32-Leads, Body 5x5mm, Pitch 0.5mm, IPC Low Density)
pins: 1 PD3 (PCINT19/OC2B/INT1) (io), 2 PD4 (PCINT20/XCK/T0) (io), 3 GND (power), 4 VCC (power), 5 GND (power), 6 VCC (power), 7 PB6 (PCINT6/XTAL1/TOSC1) (io), 8 PB7 (PCINT7/XTAL2/TOSC2) (io), 9 PD5 (PCINT21/OC0B/T1) (io), 10 PD6 (PCINT22/OC0A/AIN0) (io), 11 PD7 (PCINT23/AIN1) (io), 12 PB0 (PCINT0/CLKO/ICP1) (io), 13 PB1 (PCINT1/OC1A) (io), 14 PB2 (PCINT2/~{SS}/OC1B) (io), 15 PB3 (PCINT3/OC2A/MOSI) (io), 16 PB4 (PCINT4/MISO) (io), 17 PB5 (SCK/PCINT5) (io), 18 AVCC (power), 19 ADC6 (in), 20 AREF, 21 GND (power), 22 ADC7 (in), 23 PC0 (ADC0/PCINT8) (io), 24 PC1 (ADC1/PCINT9) (io), 25 PC2 (ADC2/PCINT10) (io), 26 PC3 (ADC3/PCINT11) (io), 27 PC4 (ADC4/SDA/PCINT12) (io), 28 PC5 (ADC5/SCL/PCINT13) (io), 29 PC6 (~{RESET}/PCINT14) (io), 30 PD0 (RXD/PCINT16) (io), 31 PD1 (TXD/PCINT17) (io), 32 PD2 (INT0/PCINT18) (io), 33 DAP (power)

## ATmega48-15MZ
designator U?
8-bit Automotive AVR Microcontroller, 4KB Flash, 256 Bytes EEPROM, 512 Bytes SRAM, Automotive Grade (-40°C to 125°C), 32-Pin VQFN
footprint 32PN_N (QFN, 32-Leads, Body 5x5mm, Pitch 0.5mm, IPC Medium Density)
footprint 32PN_L (QFN, 32-Leads, Body 5x5mm, Pitch 0.5mm, IPC High Density)
footprint 32PN_M (QFN, 32-Leads, Body 5x5mm, Pitch 0.5mm, IPC Low Density)
pins: 1 PD3 (PCINT19/OC2B/INT1) (io), 2 PD4 (PCINT20/XCK/T0) (io), 3 GND (power), 4 VCC (power), 5 GND (power), 6 VCC (power), 7 PB6 (PCINT6/XTAL1/TOSC1) (io), 8 PB7 (PCINT7/XTAL2/TOSC2) (io), 9 PD5 (PCINT21/OC0B/T1) (io), 10 PD6 (PCINT22/OC0A/AIN0) (io), 11 PD7 (PCINT23/AIN1) (io), 12 PB0 (PCINT0/CLKO/ICP1) (io), 13 PB1 (PCINT1/OC1A) (io), 14 PB2 (PCINT2/~{SS}/OC1B) (io), 15 PB3 (PCINT3/OC2A/MOSI) (io), 16 PB4 (PCINT4/MISO) (io), 17 PB5 (SCK/PCINT5) (io), 18 AVCC (power), 19 ADC6 (in), 20 AREF, 21 GND (power), 22 ADC7 (in), 23 PC0 (ADC0/PCINT8) (io), 24 PC1 (ADC1/PCINT9) (io), 25 PC2 (ADC2/PCINT10) (io), 26 PC3 (ADC3/PCINT11) (io), 27 PC4 (ADC4/SDA/PCINT12) (io), 28 PC5 (ADC5/SCL/PCINT13) (io), 29 PC6 (~{RESET}/PCINT14) (io), 30 PD0 (RXD/PCINT16) (io), 31 PD1 (TXD/PCINT17) (io), 32 PD2 (INT0/PCINT18) (io), 33 DAP (power)

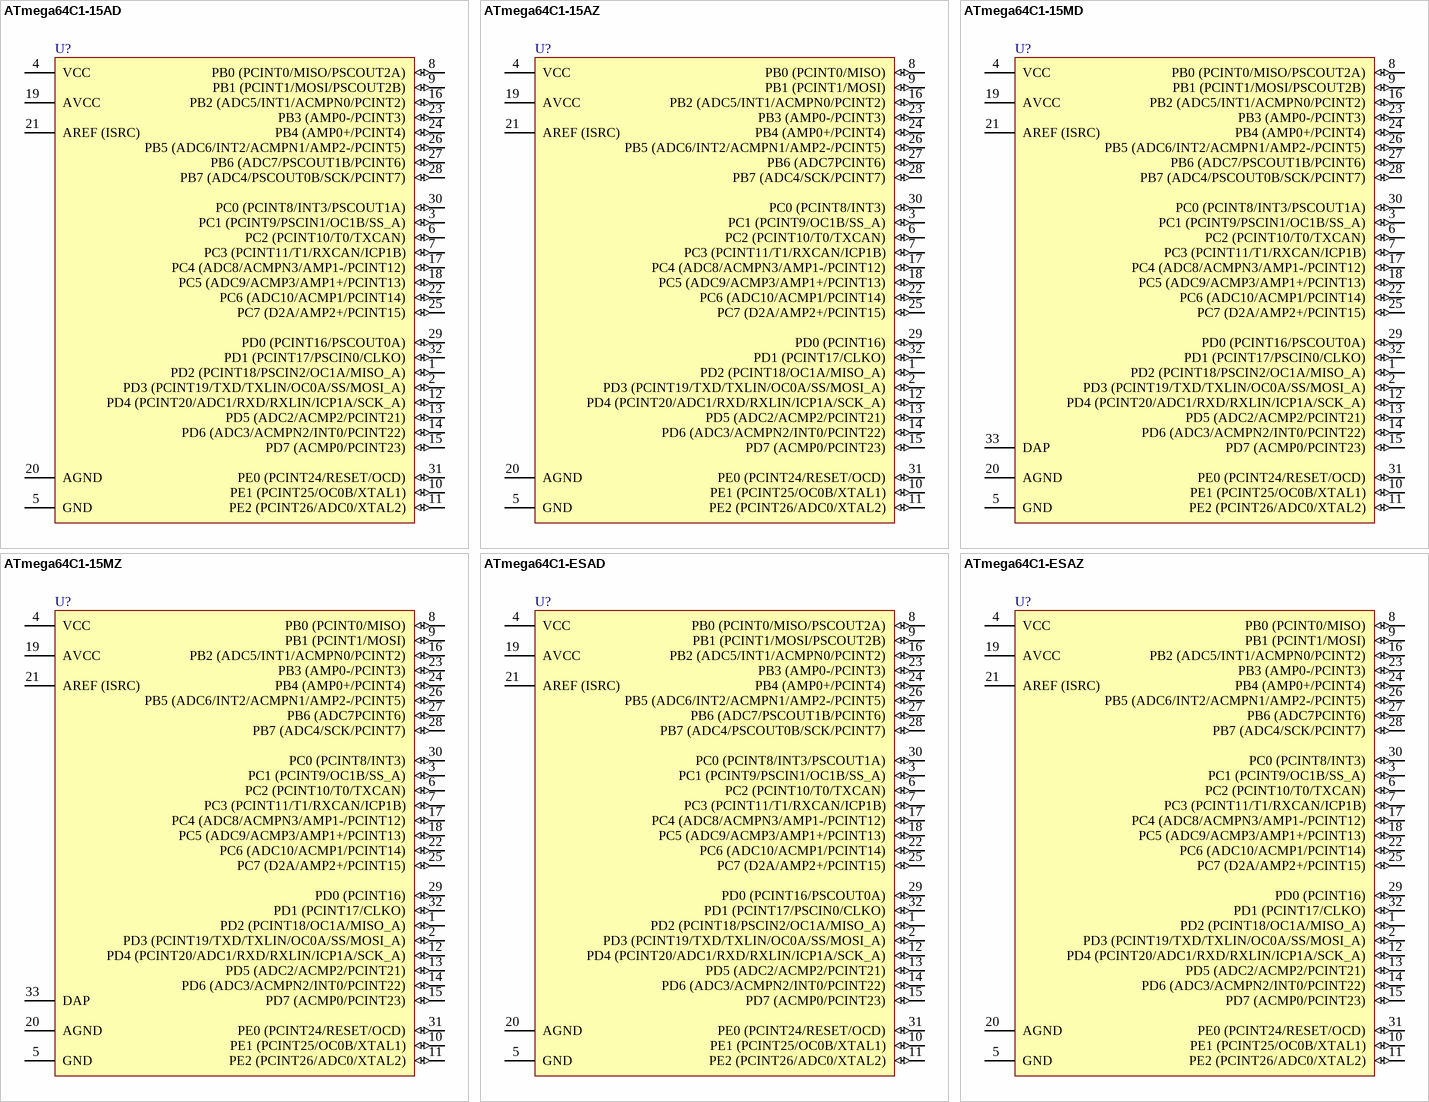
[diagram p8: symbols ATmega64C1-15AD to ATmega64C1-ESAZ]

## ATmega64C1-15AD
designator U?
8-bit Automotive AVR Microcontroller, 64KB Flash, 2KB EEPROM, 4KB SRAM, Extended Grade (-40°C to +150°C), 32-Pin TQFP
footprint 32MA_N (Thin QFP, 32-Leads, Body 7x7mm, Pitch 0.8mm, IPC Medium Density)
footprint 32MA_L (Thin QFP, 32-Leads, Body 7x7mm, Pitch 0.8mm, IPC High Density)
footprint 32MA_M (Thin QFP, 32-Leads, Body 7x7mm, Pitch 0.8mm, IPC Low Density)
pins: 1 PD2 (PCINT18/PSCIN2/OC1A/MISO_A) (io), 2 PD3 (PCINT19/TXD/TXLIN/OC0A/SS/MOSI_A) (io), 3 PC1 (PCINT9/PSCIN1/OC1B/SS_A) (io), 4 VCC (power), 5 GND (power), 6 PC2 (PCINT10/T0/TXCAN) (io), 7 PC3 (PCINT11/T1/RXCAN/ICP1B) (io), 8 PB0 (PCINT0/MISO/PSCOUT2A) (io), 9 PB1 (PCINT1/MOSI/PSCOUT2B) (io), 10 PE1 (PCINT25/OC0B/XTAL1) (io), 11 PE2 (PCINT26/ADC0/XTAL2) (io), 12 PD4 (PCINT20/ADC1/RXD/RXLIN/ICP1A/SCK_A) (io), 13 PD5 (ADC2/ACMP2/PCINT21) (io), 14 PD6 (ADC3/ACMPN2/INT0/PCINT22) (io), 15 PD7 (ACMP0/PCINT23) (io), 16 PB2 (ADC5/INT1/ACMPN0/PCINT2) (io), 17 PC4 (ADC8/ACMPN3/AMP1-/PCINT12) (io), 18 PC5 (ADC9/ACMP3/AMP1+/PCINT13) (io), 19 AVCC (power), 20 AGND (power), 21 AREF (ISRC) (power), 22 PC6 (ADC10/ACMP1/PCINT14) (io), 23 PB3 (AMP0-/PCINT3) (io), 24 PB4 (AMP0+/PCINT4) (io), 25 PC7 (D2A/AMP2+/PCINT15) (io), 26 PB5 (ADC6/INT2/ACMPN1/AMP2-/PCINT5) (io), 27 PB6 (ADC7/PSCOUT1B/PCINT6) (io), 28 PB7 (ADC4/PSCOUT0B/SCK/PCINT7) (io), 29 PD0 (PCINT16/PSCOUT0A) (io), 30 PC0 (PCINT8/INT3/PSCOUT1A) (io), 31 PE0 (PCINT24/RESET/OCD) (io), 32 PD1 (PCINT17/PSCIN0/CLKO) (io)

## ATmega64C1-15AZ
designator U?
8-bit Automotive AVR Microcontroller, 64KB Flash, 2KB EEPROM, 4KB SRAM, Automotive Grade (-40°C to +125°C), 32-Pin TQFP
footprint 32MA_N (Thin QFP, 32-Leads, Body 7x7mm, Pitch 0.8mm, IPC Medium Density)
footprint 32MA_L (Thin QFP, 32-Leads, Body 7x7mm, Pitch 0.8mm, IPC High Density)
footprint 32MA_M (Thin QFP, 32-Leads, Body 7x7mm, Pitch 0.8mm, IPC Low Density)
pins: 1 PD2 (PCINT18/OC1A/MISO_A) (io), 2 PD3 (PCINT19/TXD/TXLIN/OC0A/SS/MOSI_A) (io), 3 PC1 (PCINT9/OC1B/SS_A) (io), 4 VCC (power), 5 GND (power), 6 PC2 (PCINT10/T0/TXCAN) (io), 7 PC3 (PCINT11/T1/RXCAN/ICP1B) (io), 8 PB0 (PCINT0/MISO) (io), 9 PB1 (PCINT1/MOSI) (io), 10 PE1 (PCINT25/OC0B/XTAL1) (io), 11 PE2 (PCINT26/ADC0/XTAL2) (io), 12 PD4 (PCINT20/ADC1/RXD/RXLIN/ICP1A/SCK_A) (io), 13 PD5 (ADC2/ACMP2/PCINT21) (io), 14 PD6 (ADC3/ACMPN2/INT0/PCINT22) (io), 15 PD7 (ACMP0/PCINT23) (io), 16 PB2 (ADC5/INT1/ACMPN0/PCINT2) (io), 17 PC4 (ADC8/ACMPN3/AMP1-/PCINT12) (io), 18 PC5 (ADC9/ACMP3/AMP1+/PCINT13) (io), 19 AVCC (power), 20 AGND (power), 21 AREF (ISRC) (power), 22 PC6 (ADC10/ACMP1/PCINT14) (io), 23 PB3 (AMP0-/PCINT3) (io), 24 PB4 (AMP0+/PCINT4) (io), 25 PC7 (D2A/AMP2+/PCINT15) (io), 26 PB5 (ADC6/INT2/ACMPN1/AMP2-/PCINT5) (io), 27 PB6 (ADC7PCINT6) (io), 28 PB7 (ADC4/SCK/PCINT7) (io), 29 PD0 (PCINT16) (io), 30 PC0 (PCINT8/INT3) (io), 31 PE0 (PCINT24/RESET/OCD) (io), 32 PD1 (PCINT17/CLKO) (io)

## ATmega64C1-15MD
designator U?
8-bit Automotive AVR Microcontroller, 64KB Flash, 2KB EEPROM, 4KB SRAM, Extended Grade (-40°C to +150°C), 32-Pin VQFN
footprint 32PV_N (QFN, 32-Leads, Body 7x7 mm, Pitch 0.65mm, IPC Medium Density)
footprint 32PV_L (QFN, 32-Leads, Body 7x7 mm, Pitch 0.65mm, IPC High Density)
footprint 32PV_M (QFN, 32-Leads, Body 7x7 mm, Pitch 0.65mm, IPC Low Density)
pins: 1 PD2 (PCINT18/PSCIN2/OC1A/MISO_A) (io), 2 PD3 (PCINT19/TXD/TXLIN/OC0A/SS/MOSI_A) (io), 3 PC1 (PCINT9/PSCIN1/OC1B/SS_A) (io), 4 VCC (power), 5 GND (power), 6 PC2 (PCINT10/T0/TXCAN) (io), 7 PC3 (PCINT11/T1/RXCAN/ICP1B) (io), 8 PB0 (PCINT0/MISO/PSCOUT2A) (io), 9 PB1 (PCINT1/MOSI/PSCOUT2B) (io), 10 PE1 (PCINT25/OC0B/XTAL1) (io), 11 PE2 (PCINT26/ADC0/XTAL2) (io), 12 PD4 (PCINT20/ADC1/RXD/RXLIN/ICP1A/SCK_A) (io), 13 PD5 (ADC2/ACMP2/PCINT21) (io), 14 PD6 (ADC3/ACMPN2/INT0/PCINT22) (io), 15 PD7 (ACMP0/PCINT23) (io), 16 PB2 (ADC5/INT1/ACMPN0/PCINT2) (io), 17 PC4 (ADC8/ACMPN3/AMP1-/PCINT12) (io), 18 PC5 (ADC9/ACMP3/AMP1+/PCINT13) (io), 19 AVCC (power), 20 AGND (power), 21 AREF (ISRC) (power), 22 PC6 (ADC10/ACMP1/PCINT14) (io), 23 PB3 (AMP0-/PCINT3) (io), 24 PB4 (AMP0+/PCINT4) (io), 25 PC7 (D2A/AMP2+/PCINT15) (io), 26 PB5 (ADC6/INT2/ACMPN1/AMP2-/PCINT5) (io), 27 PB6 (ADC7/PSCOUT1B/PCINT6) (io), 28 PB7 (ADC4/PSCOUT0B/SCK/PCINT7) (io), 29 PD0 (PCINT16/PSCOUT0A) (io), 30 PC0 (PCINT8/INT3/PSCOUT1A) (io), 31 PE0 (PCINT24/RESET/OCD) (io), 32 PD1 (PCINT17/PSCIN0/CLKO) (io), 33 DAP (power)

## ATmega64C1-15MZ
designator U?
8-bit Automotive AVR Microcontroller, 64KB Flash, 2KB EEPROM, 4KB SRAM, Automotive Grade (-40°C to +125°C), 32-Pin VQFN
footprint 32PV_N (QFN, 32-Leads, Body 7x7 mm, Pitch 0.65mm, IPC Medium Density)
footprint 32PV_L (QFN, 32-Leads, Body 7x7 mm, Pitch 0.65mm, IPC High Density)
footprint 32PV_M (QFN, 32-Leads, Body 7x7 mm, Pitch 0.65mm, IPC Low Density)
pins: 1 PD2 (PCINT18/OC1A/MISO_A) (io), 2 PD3 (PCINT19/TXD/TXLIN/OC0A/SS/MOSI_A) (io), 3 PC1 (PCINT9/OC1B/SS_A) (io), 4 VCC (power), 5 GND (power), 6 PC2 (PCINT10/T0/TXCAN) (io), 7 PC3 (PCINT11/T1/RXCAN/ICP1B) (io), 8 PB0 (PCINT0/MISO) (io), 9 PB1 (PCINT1/MOSI) (io), 10 PE1 (PCINT25/OC0B/XTAL1) (io), 11 PE2 (PCINT26/ADC0/XTAL2) (io), 12 PD4 (PCINT20/ADC1/RXD/RXLIN/ICP1A/SCK_A) (io), 13 PD5 (ADC2/ACMP2/PCINT21) (io), 14 PD6 (ADC3/ACMPN2/INT0/PCINT22) (io), 15 PD7 (ACMP0/PCINT23) (io), 16 PB2 (ADC5/INT1/ACMPN0/PCINT2) (io), 17 PC4 (ADC8/ACMPN3/AMP1-/PCINT12) (io), 18 PC5 (ADC9/ACMP3/AMP1+/PCINT13) (io), 19 AVCC (power), 20 AGND (power), 21 AREF (ISRC) (power), 22 PC6 (ADC10/ACMP1/PCINT14) (io), 23 PB3 (AMP0-/PCINT3) (io), 24 PB4 (AMP0+/PCINT4) (io), 25 PC7 (D2A/AMP2+/PCINT15) (io), 26 PB5 (ADC6/INT2/ACMPN1/AMP2-/PCINT5) (io), 27 PB6 (ADC7PCINT6) (io), 28 PB7 (ADC4/SCK/PCINT7) (io), 29 PD0 (PCINT16) (io), 30 PC0 (PCINT8/INT3) (io), 31 PE0 (PCINT24/RESET/OCD) (io), 32 PD1 (PCINT17/CLKO) (io), 33 DAP (power)

## ATmega64C1-ESAD
designator U?
8-bit Automotive AVR Microcontroller, 64KB Flash, 2KB EEPROM, 4KB SRAM, Engineering Sample, 32-Pin TQFP
footprint 32MA_N (Thin QFP, 32-Leads, Body 7x7mm, Pitch 0.8mm, IPC Medium Density)
footprint 32MA_L (Thin QFP, 32-Leads, Body 7x7mm, Pitch 0.8mm, IPC High Density)
footprint 32MA_M (Thin QFP, 32-Leads, Body 7x7mm, Pitch 0.8mm, IPC Low Density)
pins: 1 PD2 (PCINT18/PSCIN2/OC1A/MISO_A) (io), 2 PD3 (PCINT19/TXD/TXLIN/OC0A/SS/MOSI_A) (io), 3 PC1 (PCINT9/PSCIN1/OC1B/SS_A) (io), 4 VCC (power), 5 GND (power), 6 PC2 (PCINT10/T0/TXCAN) (io), 7 PC3 (PCINT11/T1/RXCAN/ICP1B) (io), 8 PB0 (PCINT0/MISO/PSCOUT2A) (io), 9 PB1 (PCINT1/MOSI/PSCOUT2B) (io), 10 PE1 (PCINT25/OC0B/XTAL1) (io), 11 PE2 (PCINT26/ADC0/XTAL2) (io), 12 PD4 (PCINT20/ADC1/RXD/RXLIN/ICP1A/SCK_A) (io), 13 PD5 (ADC2/ACMP2/PCINT21) (io), 14 PD6 (ADC3/ACMPN2/INT0/PCINT22) (io), 15 PD7 (ACMP0/PCINT23) (io), 16 PB2 (ADC5/INT1/ACMPN0/PCINT2) (io), 17 PC4 (ADC8/ACMPN3/AMP1-/PCINT12) (io), 18 PC5 (ADC9/ACMP3/AMP1+/PCINT13) (io), 19 AVCC (power), 20 AGND (power), 21 AREF (ISRC) (power), 22 PC6 (ADC10/ACMP1/PCINT14) (io), 23 PB3 (AMP0-/PCINT3) (io), 24 PB4 (AMP0+/PCINT4) (io), 25 PC7 (D2A/AMP2+/PCINT15) (io), 26 PB5 (ADC6/INT2/ACMPN1/AMP2-/PCINT5) (io), 27 PB6 (ADC7/PSCOUT1B/PCINT6) (io), 28 PB7 (ADC4/PSCOUT0B/SCK/PCINT7) (io), 29 PD0 (PCINT16/PSCOUT0A) (io), 30 PC0 (PCINT8/INT3/PSCOUT1A) (io), 31 PE0 (PCINT24/RESET/OCD) (io), 32 PD1 (PCINT17/PSCIN0/CLKO) (io)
